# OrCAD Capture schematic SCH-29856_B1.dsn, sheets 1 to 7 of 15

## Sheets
1 01 COVER: title: MIMXRT1020-EVK; rev: B1; company: Freescale Semiconductor; note: SCH-29856, PDF: SPF-29856; note: 6501 William Cannon Drive West; note: Austin, TX 78735-8598
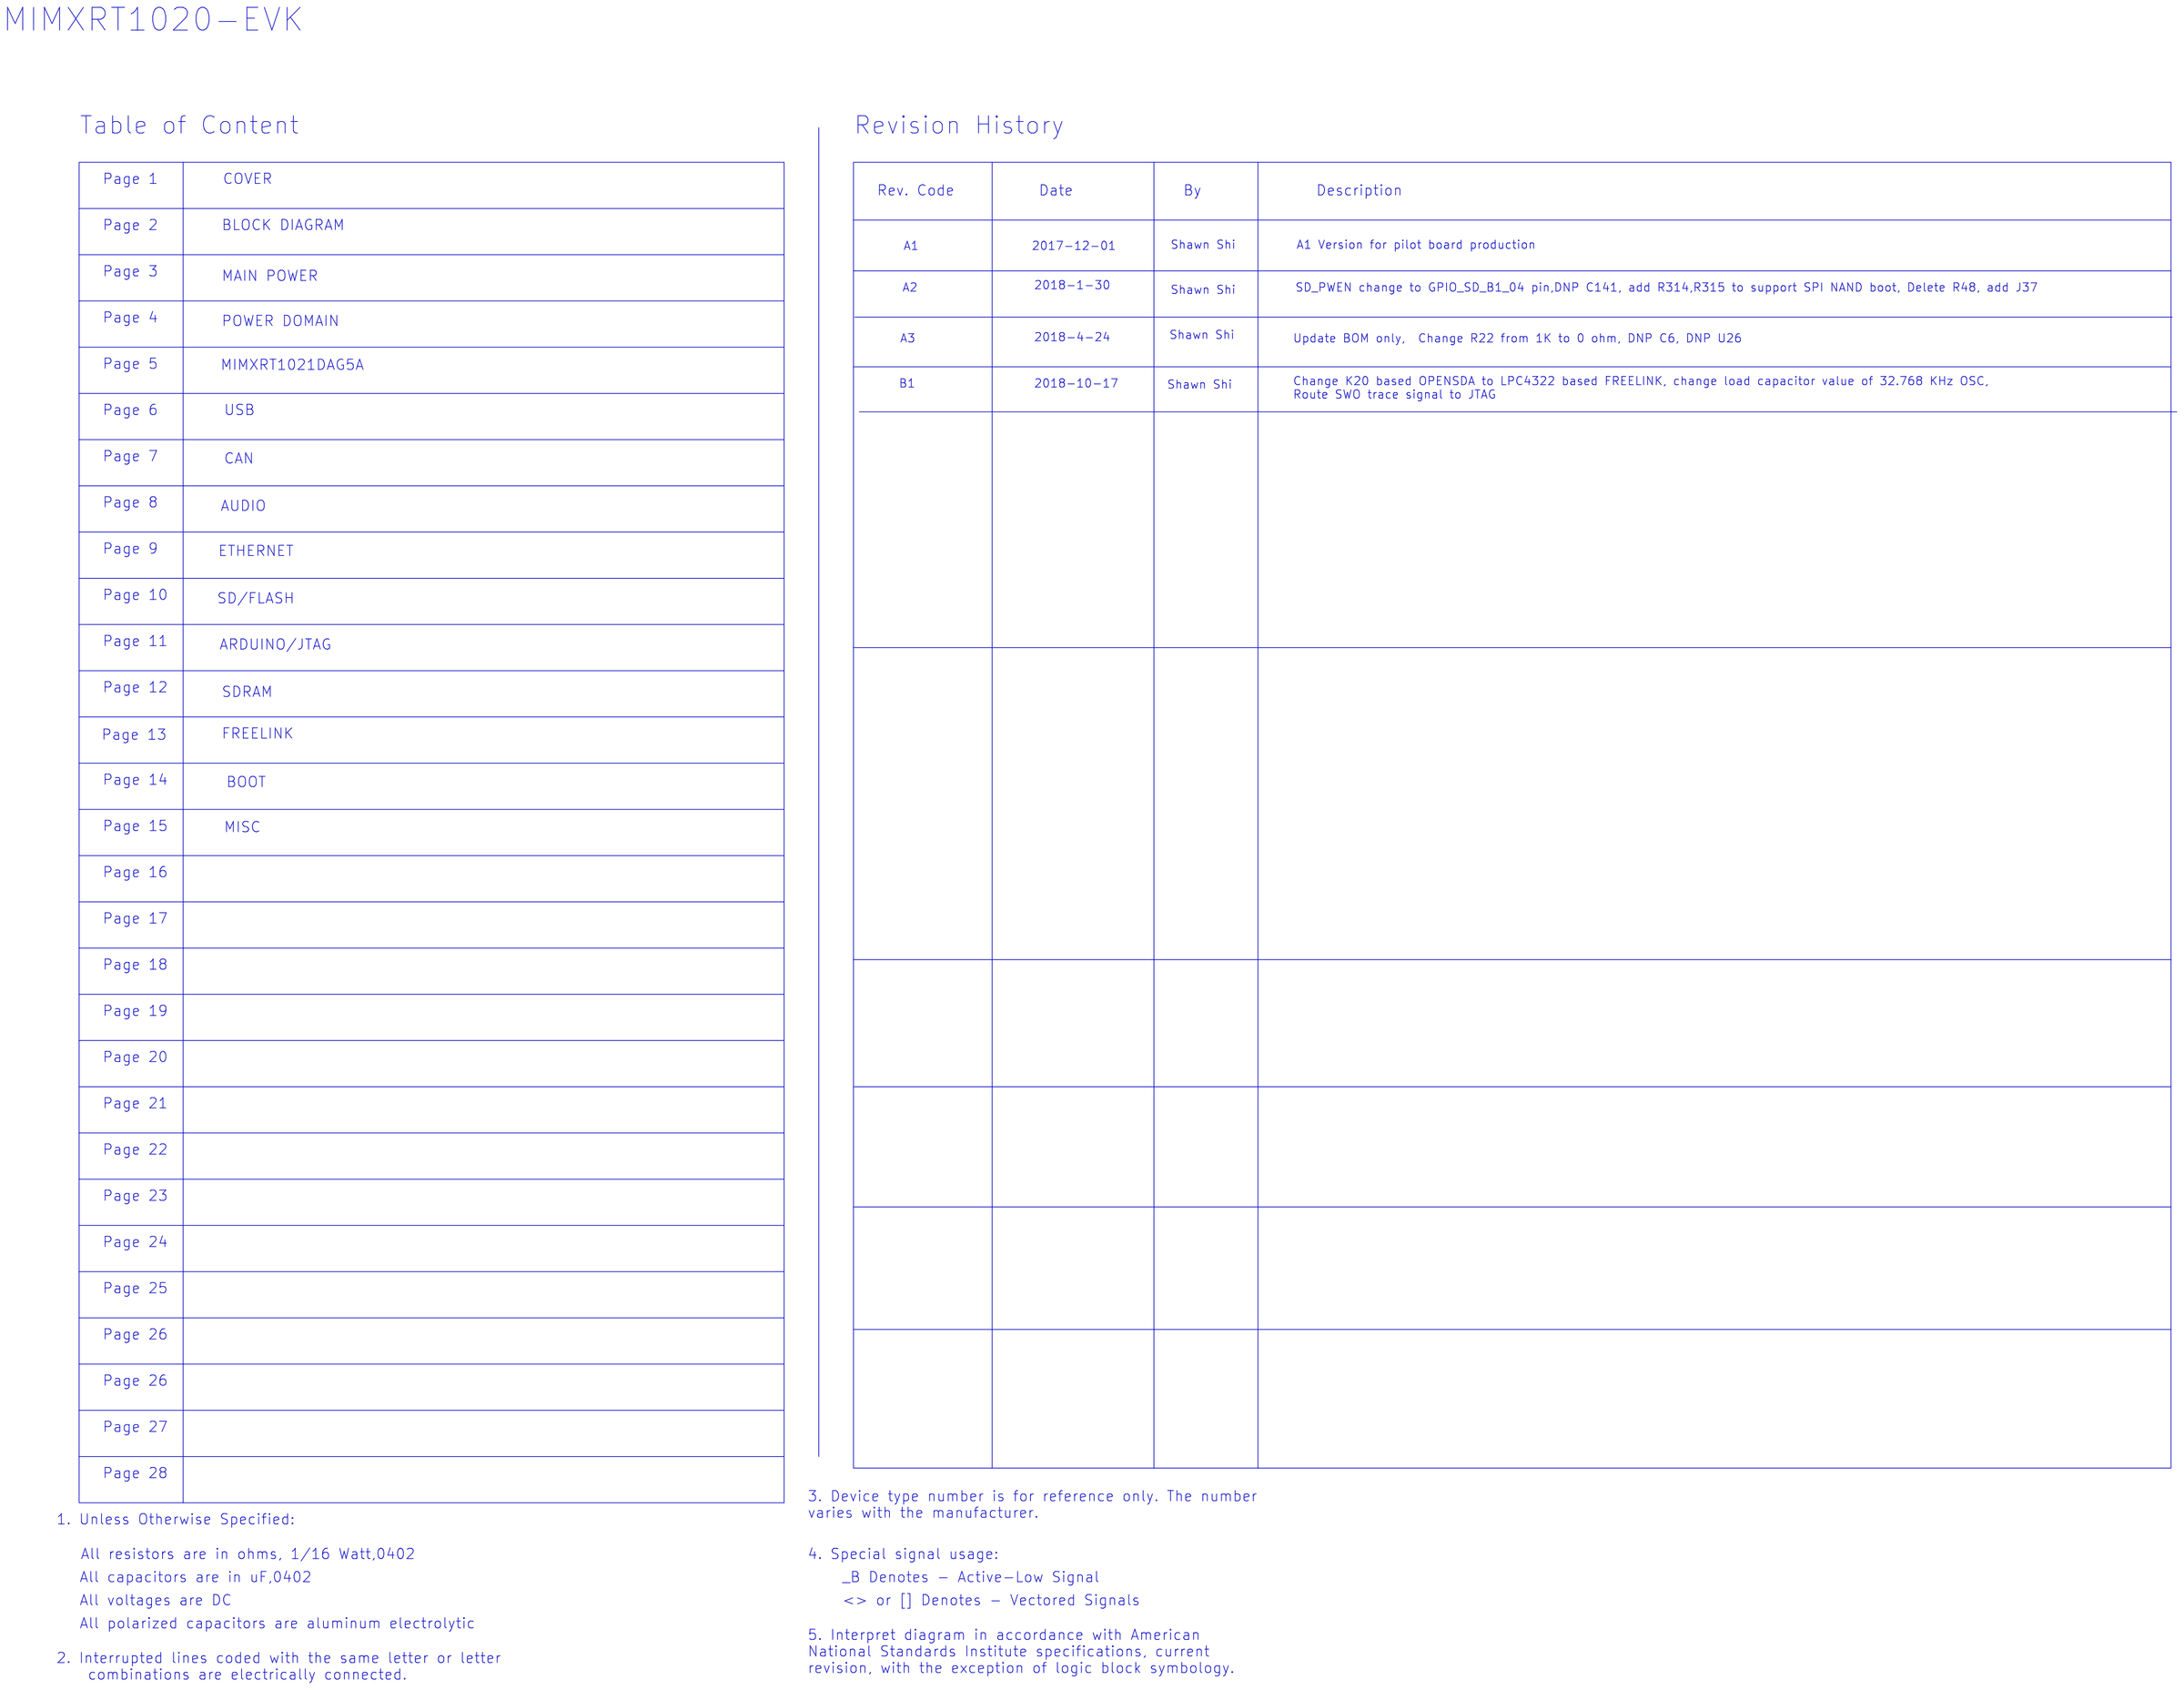
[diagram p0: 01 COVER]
2 02 BLOCK DIAGRAM
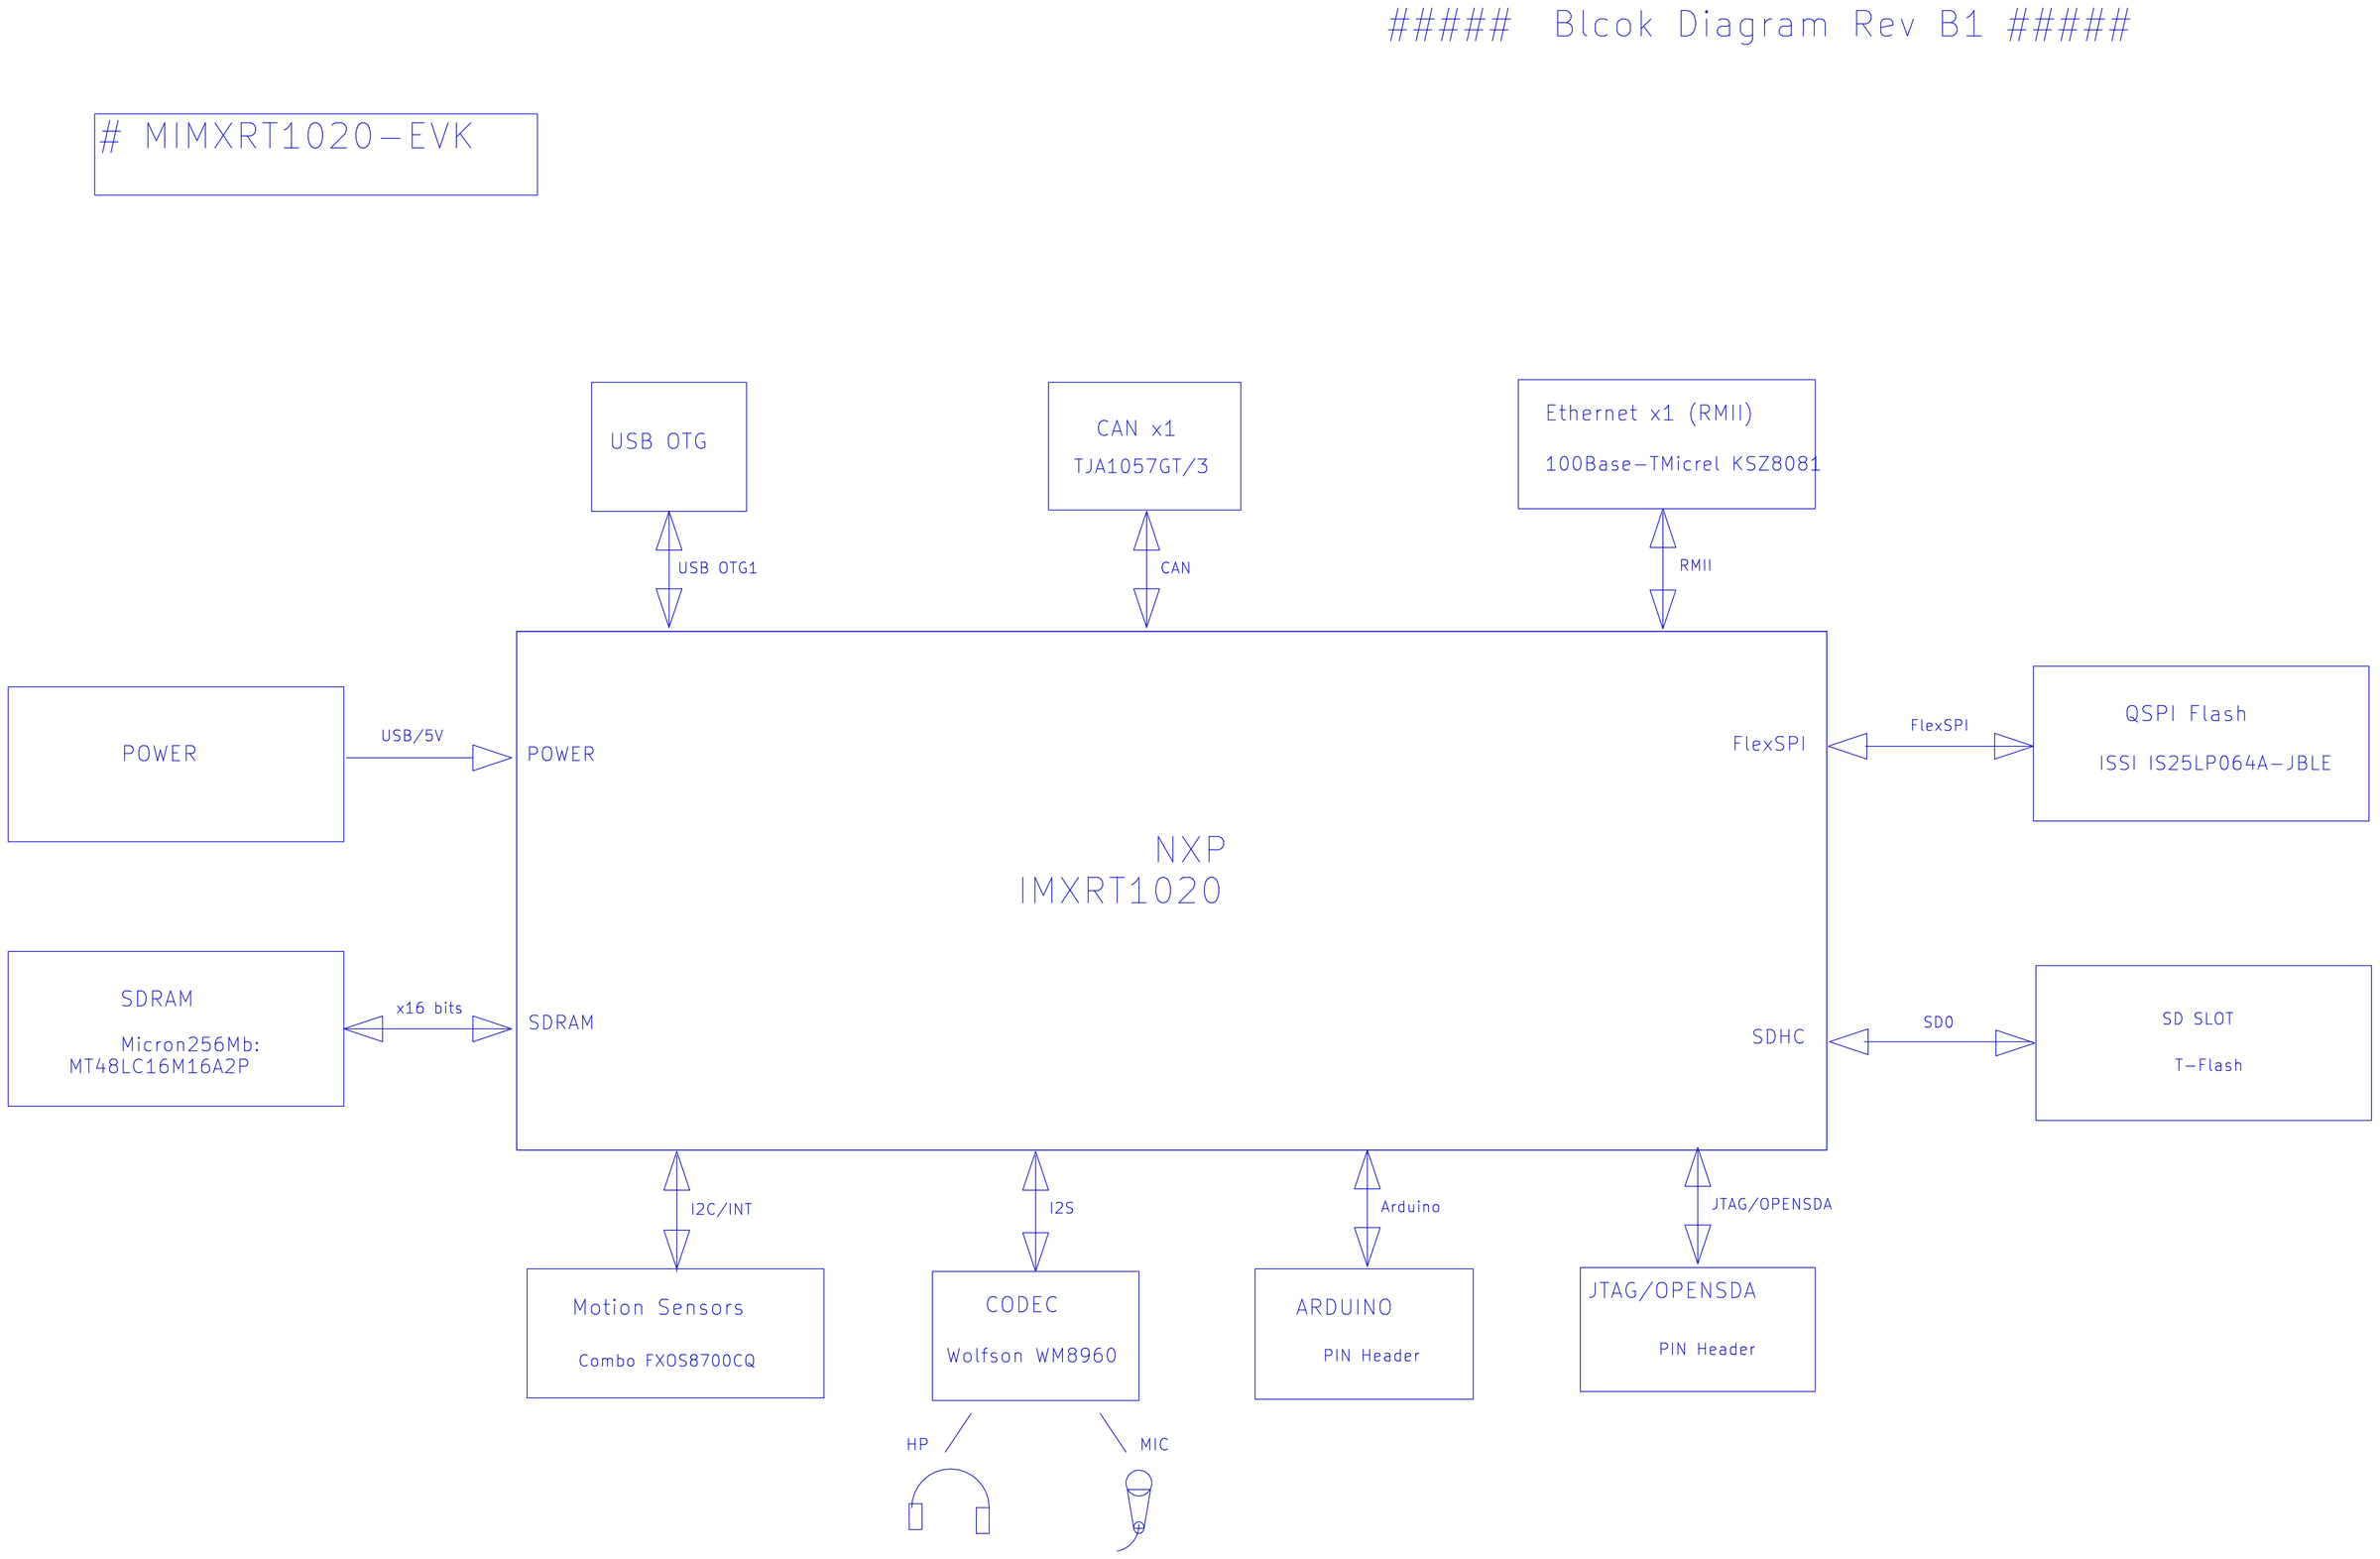
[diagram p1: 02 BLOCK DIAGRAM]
3 03 MAIN POWER: size C
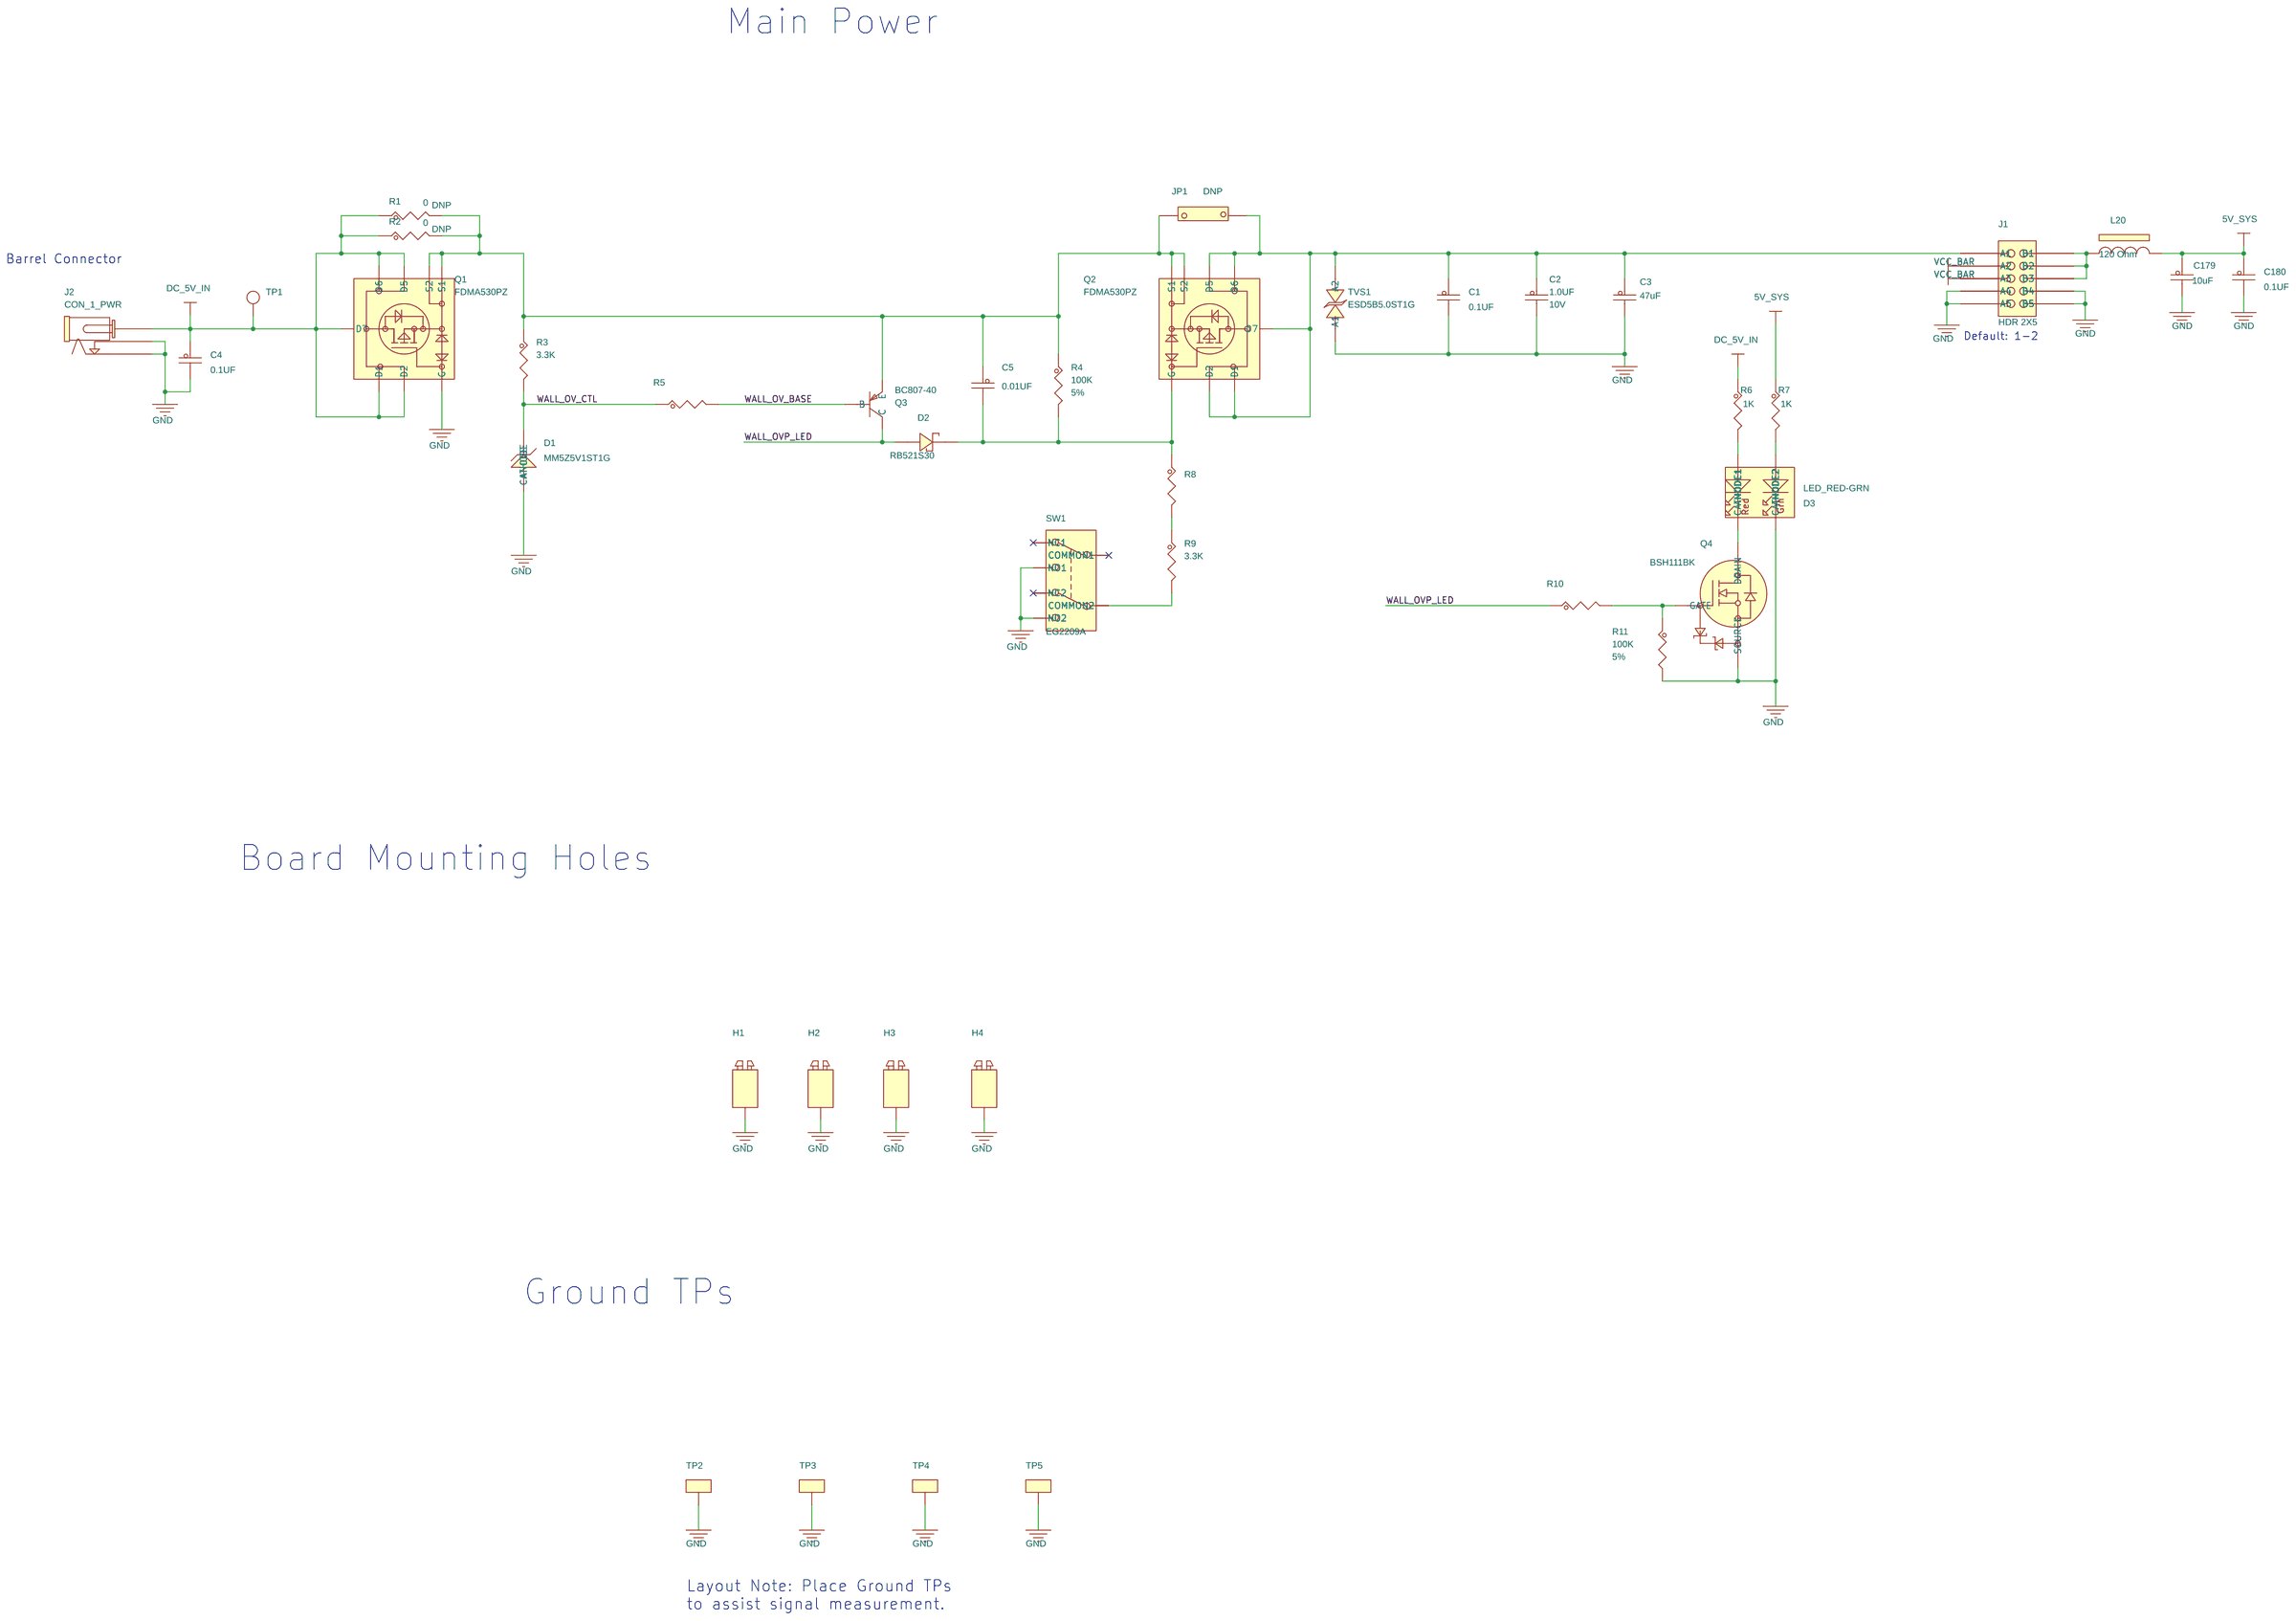
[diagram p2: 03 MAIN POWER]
4 04 POWER DOMAIN: size D
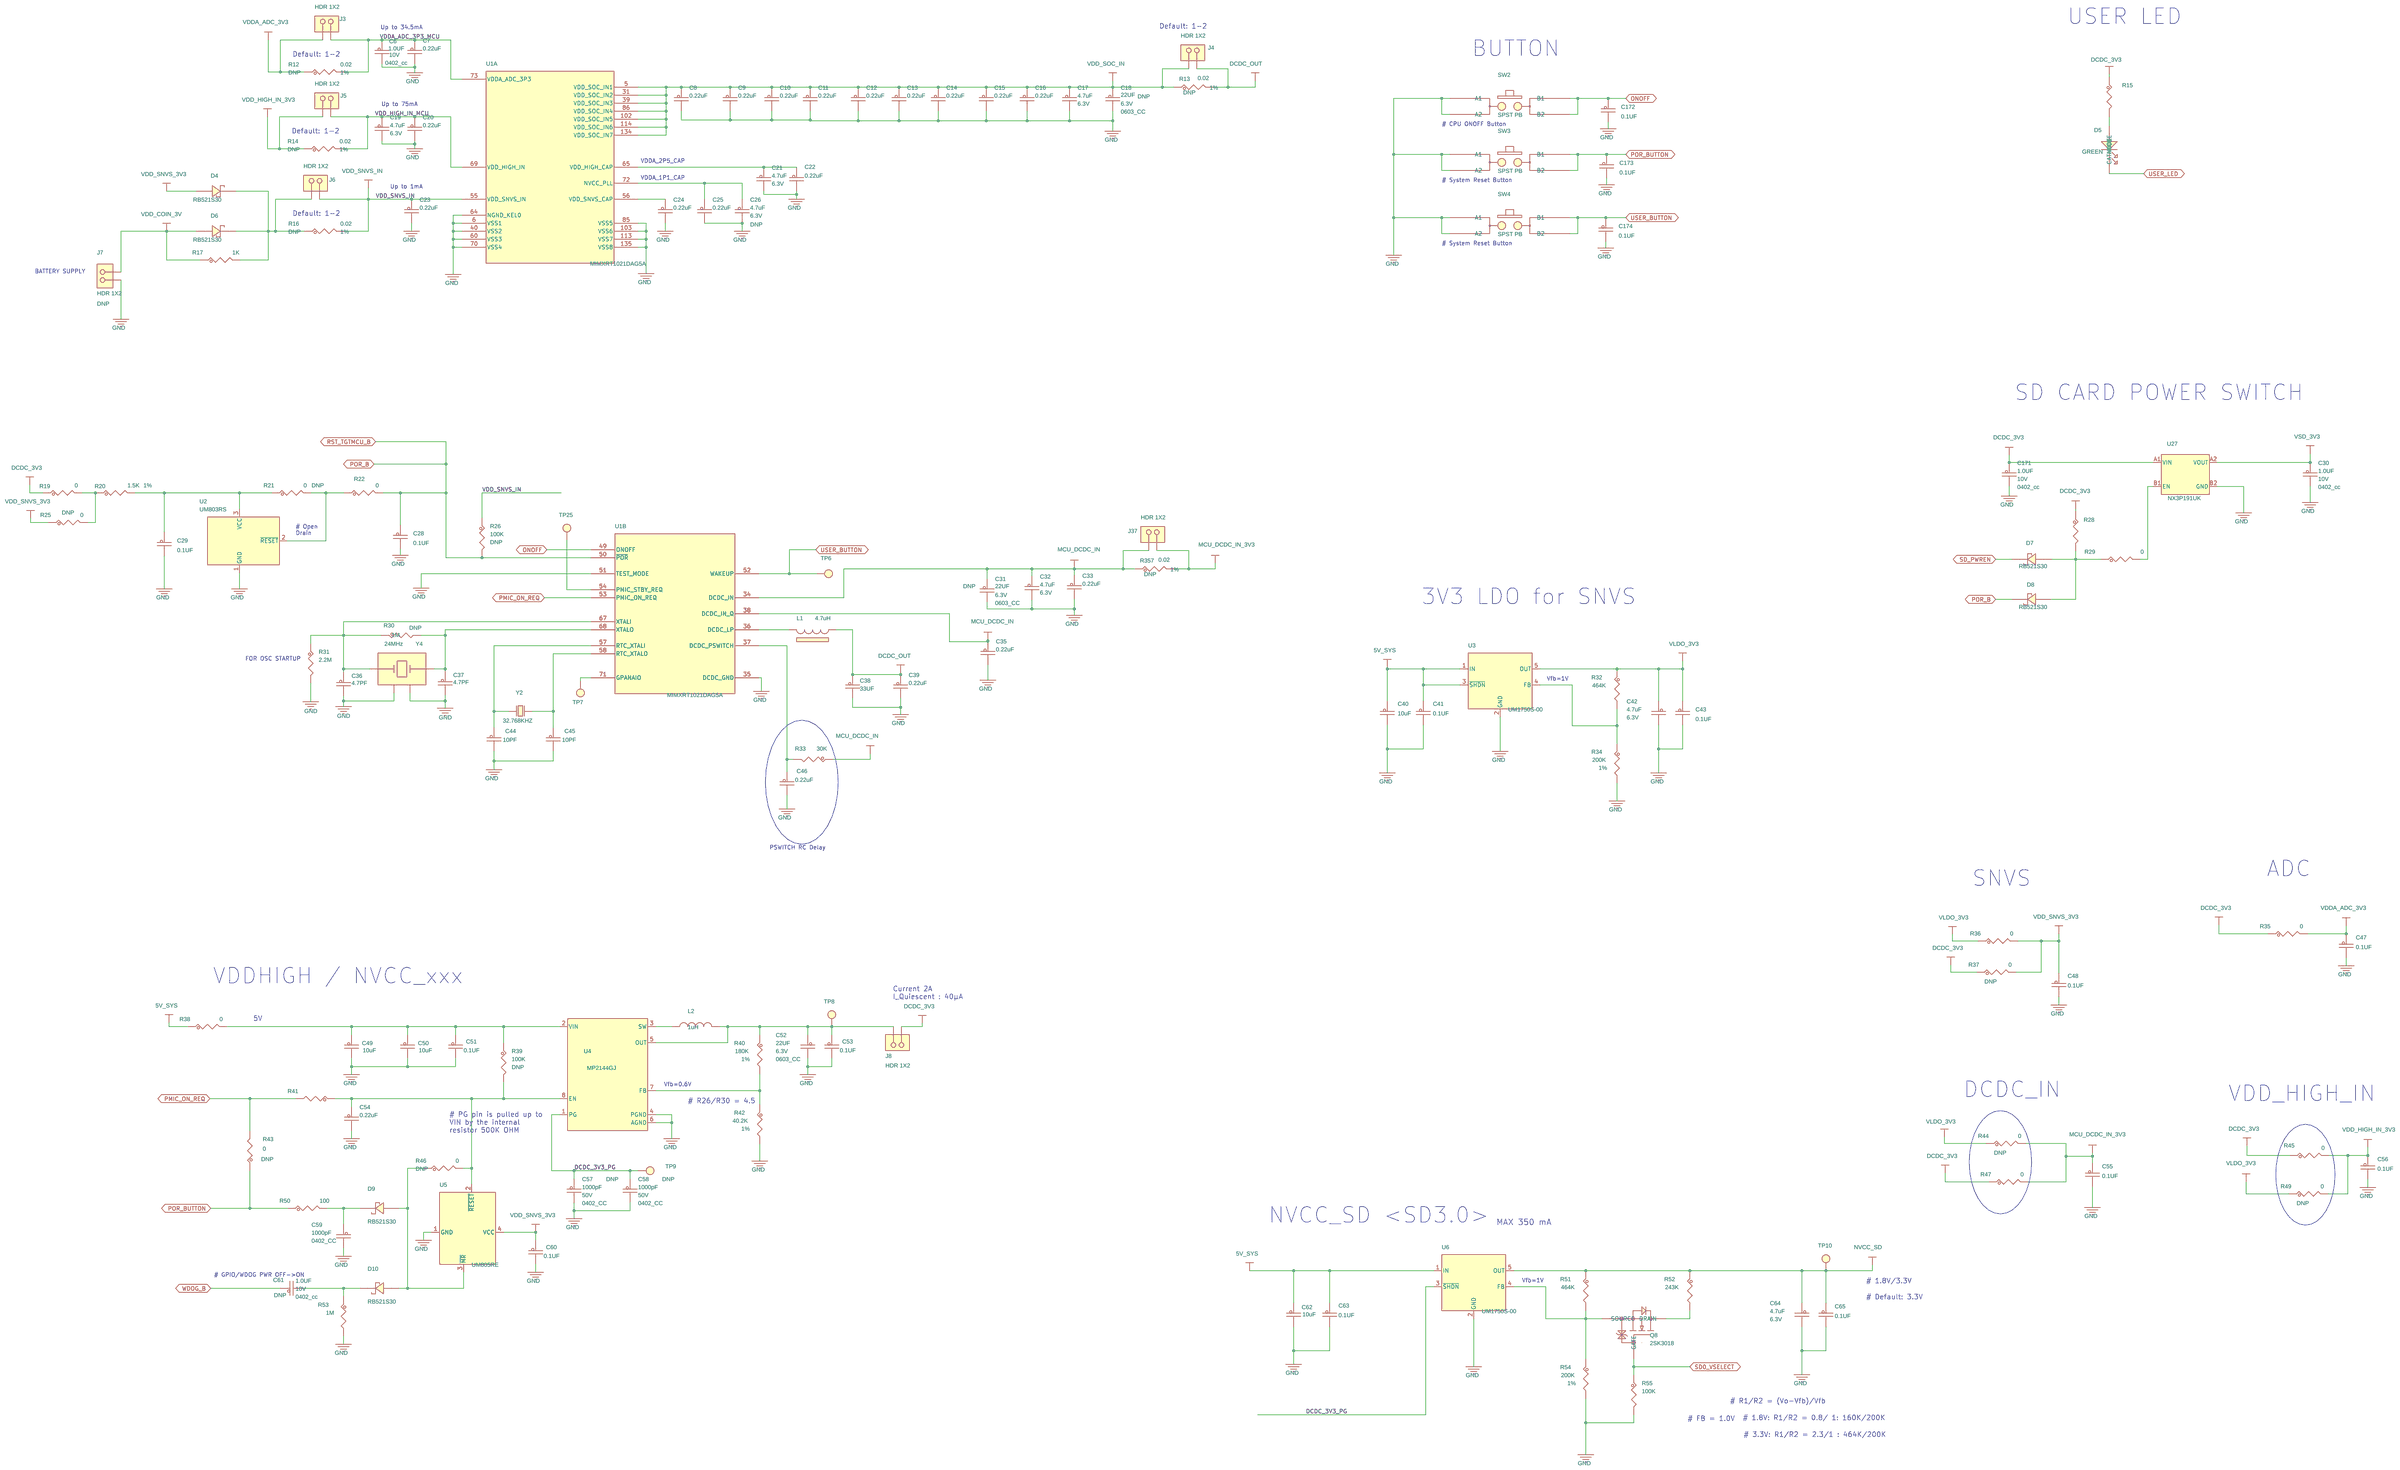
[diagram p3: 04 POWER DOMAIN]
5 05 MIMXRT1021DAG5A: size C
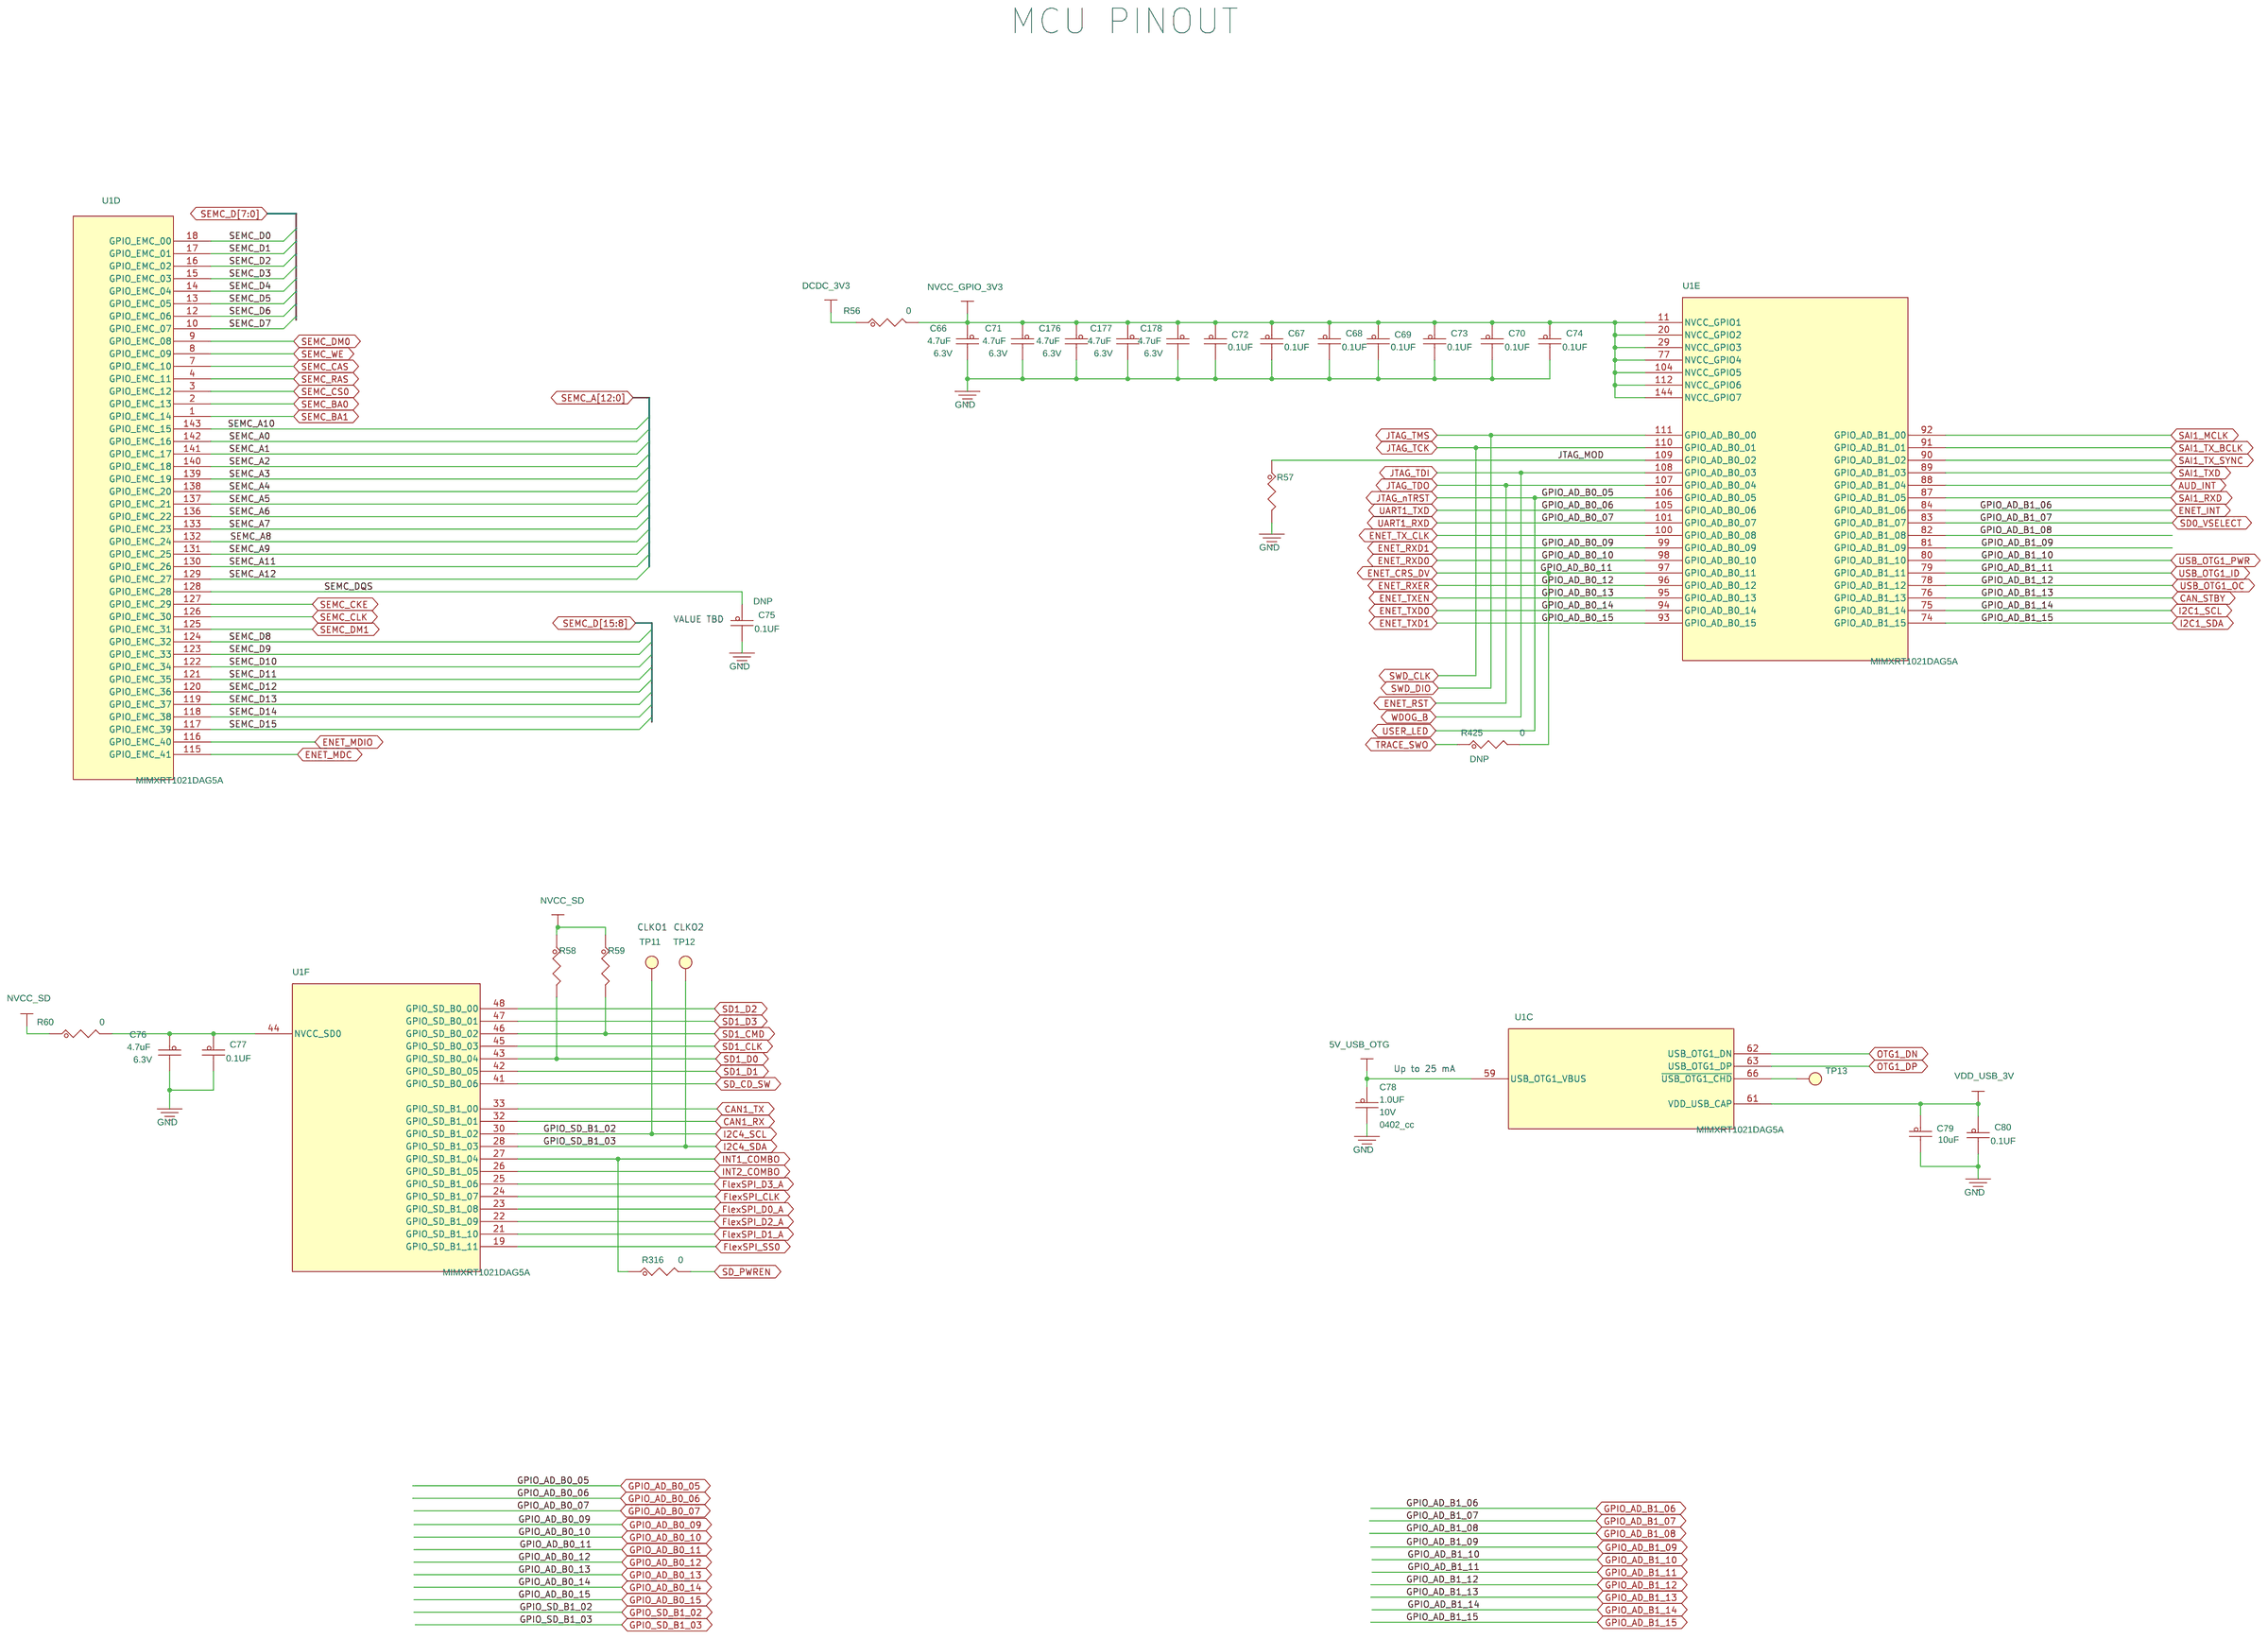
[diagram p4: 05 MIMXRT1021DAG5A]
6 06 USB: size C
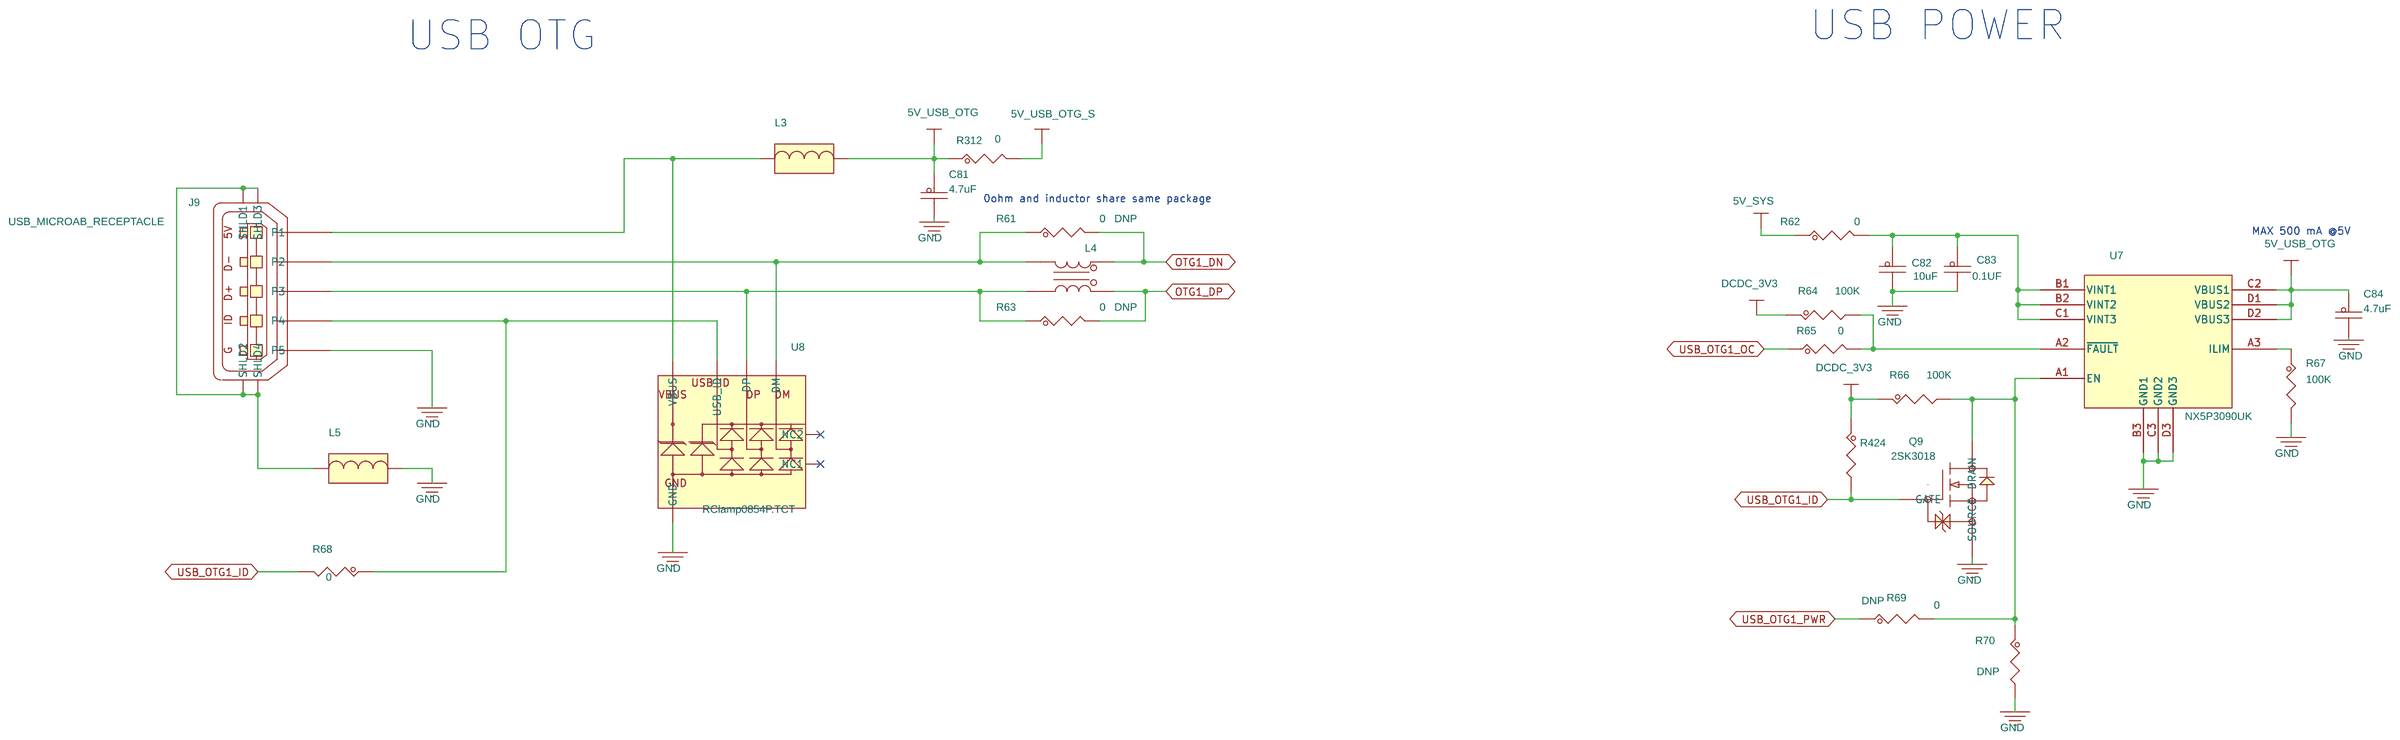
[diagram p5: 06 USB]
7 07 CAN: size C
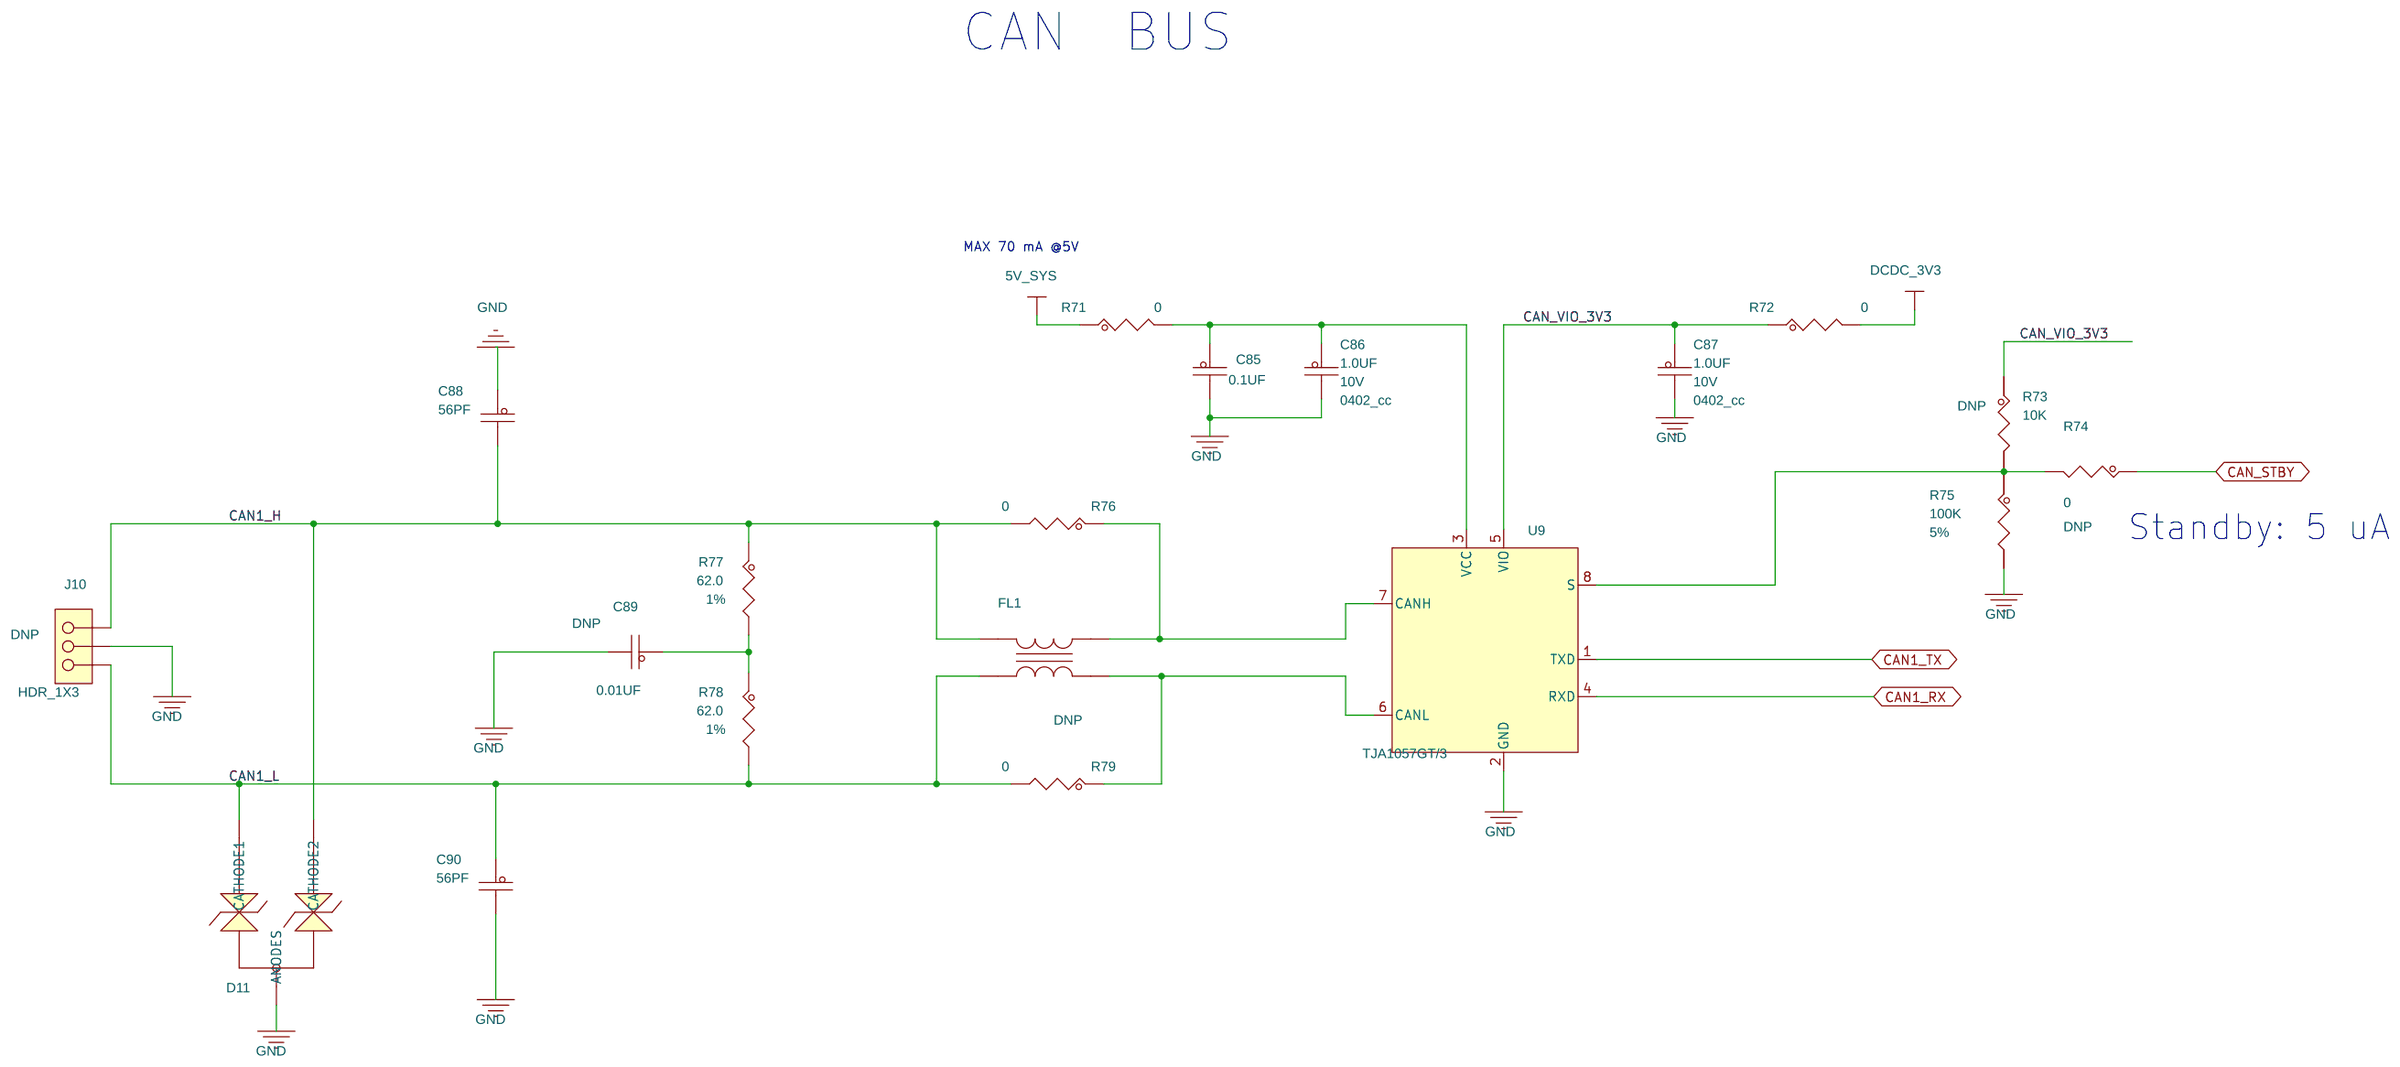
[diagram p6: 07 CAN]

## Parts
sheet 03 MAIN POWER
C1  0.1UF  [CC0402_25]
C2  1.0UF  [0402_CC]
C3  47uF  [CC1206_OV]
C4  0.1UF  [CC0402_25]
C5  0.01UF  [CC0402_25]
C179  10uF  [CC0603_OV]
C180  0.1UF  [CC0402_25]
D1  MM5Z5V1ST1G  [sod_523_1p4]
D2  RB521S30  [SOD523]
D3  LED_RED-GRN  [LED_DUAL_3025MM_SM]
H1  .635" LONG  [spacer_139t]
H2  .635" LONG  [spacer_139t]
H3  .635" LONG  [spacer_139t]
H4  .635" LONG  [spacer_139t]
J1  HDR 2X5  [hdr205]
J2  CON_1_PWR  [con3_pwr_th]
JP1  SHORT_100mil  [100MIL_TH]
L20  120 Ohm  [0402_CC]
Q1  FDMA530PZ  [MLP6_2X2MM_SLUG]
Q2  FDMA530PZ  [MLP6_2X2MM_SLUG]
Q3  BC807-40  [SOT-23]
Q4  BSH111BK  [SOT23_A]
R1  0  [0402_CC]
R2  0  [0402_CC]
R3  3.3K  [RC0402_25]
R4  100K  [0402_CC]
R5  10K  [0402_CC]
R6  1K  [0402_CC]
R7  1K  [0402_CC]
R8  2.2K  [RC0402_25]
R9  3.3K  [RC0402_25]
R10  10K  [0402_CC]
R11  100K  [0402_CC]
SW1  EG2209A  [sw6_dpdt_11x6mm]
TP1  TPAD_030  [TPAD_030]
TP2  5006  [tp_th_063]
TP3  5006  [tp_th_063]
TP4  5006  [tp_th_063]
TP5  5006  [tp_th_063]
TVS1  ESD5B5.0ST1G  [diode2_sod523]
sheet 04 POWER DOMAIN
C6  1.0UF  [0402_cc]
C7  0.22uF  [0402_CC]
C8  0.22uF  [0402_CC]
C9  0.22uF  [0402_CC]
C10  0.22uF  [0402_CC]
C11  0.22uF  [0402_CC]
C12  0.22uF  [0402_CC]
C13  0.22uF  [0402_CC]
C14  0.22uF  [0402_CC]
C15  0.22uF  [0402_CC]
C16  0.22uF  [0402_CC]
C17  4.7uF  [0402_CC]
C18  22UF  [0603_CC]
C19  4.7uF  [0402_CC]
C20  0.22uF  [0402_CC]
C21  4.7uF  [0402_CC]
C22  0.22uF  [0402_CC]
C23  0.22uF  [0402_CC]
C24  0.22uF  [0402_CC]
C25  0.22uF  [0402_CC]
C26  4.7uF  [0402_CC]
C28  0.1UF  [CC0402_25]
C29  0.1UF  [CC0402_25]
C30  1.0UF  [0402_cc]
C31  22UF  [0603_CC]
C32  4.7uF  [0402_CC]
C33  0.22uF  [0402_CC]
C35  0.22uF  [0402_CC]
C36  4.7PF  [0402_CC]
C37  4.7PF  [0402_CC]
C38  33UF  [CC1210]
C39  0.22uF  [0402_CC]
C40  10uF  [CC0603_OV]
C41  0.1UF  [CC0402_25]
C42  4.7uF  [0402_CC]
C43  0.1UF  [CC0402_25]
C44  10PF  [0402_CC]
C45  10PF  [0402_CC]
C46  0.22uF  [0402_CC]
C47  0.1UF  [CC0402_25]
C48  0.1UF  [CC0402_25]
C49  10uF  [CC0603_OV]
C50  10uF  [CC0603_OV]
C51  0.1UF  [CC0402_25]
C52  22UF  [0603_CC]
C53  0.1UF  [CC0402_25]
C54  0.22uF  [0402_CC]
C55  0.1UF  [CC0402_25]
C56  0.1UF  [CC0402_25]
C57  1000pF  [0402_CC]
C58  1000pF  [0402_CC]
C59  1000pF  [0402_CC]
C60  0.1UF  [CC0402_25]
C61  1.0UF  [0402_cc]
C62  10uF  [CC0603_OV]
C63  0.1UF  [CC0402_25]
C64  4.7uF  [0402_CC]
C65  0.1UF  [CC0402_25]
C171  1.0UF  [0402_cc]
C172  0.1UF  [CC0402_25]
C173  0.1UF  [CC0402_25]
C174  0.1UF  [CC0402_25]
D4  RB521S30  [SOD523]
D5  GREEN  [LED_0603]
D6  RB521S30  [SOD523]
D7  RB521S30  [SOD523]
D8  RB521S30  [SOD523]
D9  RB521S30  [SOD523]
D10  RB521S30  [SOD523]
J3  HDR 1X2  [HDR102]
J4  HDR 1X2  [HDR102]
J5  HDR 1X2  [HDR102]
J6  HDR 1X2  [HDR102]
J7  HDR 1X2  [HDR102]
J8  HDR 1X2  [HDR102]
J37  HDR 1X2  [HDR102]
L1  4.7uH  [ind_vls4012e]
L2  1uH  [ind_4020]
Q8  2SK3018  [SOT323_3]
R12  0.02  [RC0603_OV]
R13  0.02  [RC0603_OV]
R14  0.02  [RC0603_OV]
R15  220  [RC0603_OV]
R16  0.02  [RC0603_OV]
R17  1K  [0402_CC]
R19  0  [0402_CC]
R20  1.5K  [0402_CC]
R21  0  [0402_CC]
R22  0  [0402_CC]
R25  0  [0402_CC]
R26  100K  [0402_CC]
R28  10K  [0402_CC]
R29  0  [0402_CC]
R30  1M  [0402_CC]
R31  2.2M  [RC0402_25]
R32  464K  [0402_CC]
R33  30K  [RC0402_25]
R34  200K  [0402_CC]
R35  0  [0402_CC]
R36  0  [0402_CC]
R37  0  [0402_CC]
R38  0  [0402_CC]
R39  100K  [0402_CC]
R40  180K  [0402_CC]
R41  10K  [0402_CC]
R42  40.2K  [0402_CC]
R43  0  [0402_CC]
R44  0  [0402_CC]
R45  0  [0402_CC]
R46  0  [0402_CC]
R47  0  [0402_CC]
R49  0  [0402_CC]
R50  100  [0402_CC]
R51  464K  [0402_CC]
R52  243K  [0402_CC]
R53  1M  [0402_CC]
R54  200K  [0402_CC]
R55  100K  [0402_CC]
R357  0.02  [RC0603_OV]
SW2  SPST PB  [SW4_PB_ESW_SM_P177]
SW3  SPST PB  [SW4_PB_ESW_SM_P177]
SW4  SPST PB  [SW4_PB_ESW_SM_P177]
TP6  TP_35MIL  [testpoint_35mil]
TP7  TP_35MIL  [testpoint_35mil]
TP8  TP_35MIL  [testpoint_35mil]
TP9  TP_35MIL  [testpoint_35mil]
TP10  TP_35MIL  [testpoint_35mil]
TP25  TP_35MIL  [testpoint_35mil]
U1  MIMXRT1021DAG5A  [LQFP144_0P5_20X20MM]  (sections A,B,C,D,E,F)
U2  UM803RS  [sot-23]
U3  UM1750S-00  [sot23-5_a]
U4  MP2144GJ  [tsot23_8_0p65_2x1]
U5  UM805RE  [sot_143]
U6  UM1750S-00  [sot23-5_a]
U27  NX3P191UK  [wlcsp4_0p4_0p8x0p8_smdp]
Y2  32.768KHZ  [XTAL2-3p2x1p5-SM]
Y4  24MHz  [xtl4_2p1x1p7mm_sm]
sheet 05 MIMXRT1021DAG5A
C66  4.7uF  [0402_CC]
C67  0.1UF  [CC0402_25]
C68  0.1UF  [CC0402_25]
C69  0.1UF  [CC0402_25]
C70  0.1UF  [CC0402_25]
C71  4.7uF  [0402_CC]
C72  0.1UF  [CC0402_25]
C73  0.1UF  [CC0402_25]
C74  0.1UF  [CC0402_25]
C75  0.1UF  [CC0402_25]
C76  4.7uF  [0402_CC]
C77  0.1UF  [CC0402_25]
C78  1.0UF  [0402_cc]
C79  10uF  [CC0603_OV]
C80  0.1UF  [CC0402_25]
C176  4.7uF  [0402_CC]
C177  4.7uF  [0402_CC]
C178  4.7uF  [0402_CC]
R56  0  [0402_CC]
R57  10K  [0402_CC]
R58  10K  [0402_CC]
R59  10K  [0402_CC]
R60  0  [0402_CC]
R316  0  [0402_CC]
R425  0  [0402_CC]
TP11  TP_35MIL  [testpoint_35mil]
TP12  TP_35MIL  [testpoint_35mil]
TP13  TP_35MIL  [testpoint_35mil]
sheet 06 USB
C81  4.7uF  [0402_CC]
C82  10uF  [CC0603_OV]
C83  0.1UF  [CC0402_25]
C84  4.7uF  [0402_CC]
J9  USB_MICROAB_RECEPTACLE  [con_usb5_microab_0p65_sm]
L3  330 OHM  [ind_1608]
L4  90OHM  [ind4_choke_0805]
L5  330 OHM  [ind_1608]
Q9  2SK3018  [SOT323_3]
R61  0  [0402_CC]
R62  0  [0402_CC]
R63  0  [0402_CC]
R64  100K  [0402_CC]
R65  0  [0402_CC]
R66  100K  [0402_CC]
R67  100K  [RC0402_25]
R68  0  [0402_CC]
R69  0  [0402_CC]
R70  10K  [0402_CC]
R312  0  [0402_CC]
R424  10K  [0402_CC]
U7  NX5P3090UK  [wlcsp12_0p4_1p38x1p68mm_smdp]
U8  RClamp0854P.TCT  [slp1616p6]
sheet 07 CAN
C85  0.1UF  [CC0402_25]
C86  1.0UF  [0402_cc]
C87  1.0UF  [0402_cc]
C88  56PF  [CC0402_25]
C89  0.01UF  [CC0402_25]
C90  56PF  [CC0402_25]
D11  NUP2105L  [sot-23]
FL1  ACT45B-510-2P  [ind4_4p7x3p4_smt]
J10  HDR_1X3  [HDR103]
R71  0  [0402_CC]
R72  0  [0402_CC]
R73  10K  [0402_CC]
R74  0  [0402_CC]
R75  100K  [0402_CC]
R76  0  [0402_CC]
R77  62.0  [0805_CC]
R78  62.0  [0805_CC]
R79  0  [0402_CC]
U9  TJA1057GT/3  [SO8_1P27_4X5]

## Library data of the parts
C1 C4 C28 C29 C41 C43 C47 C48 C51 C53 C55 C56 C60 C63 C65 C67-C70 C72-C74 C77 C80 C83 C85 C172-C174 C180 = CAP_NP: CAP CER 0.1UF 10V 10% X5R 0402; AGILE_PN: 150-75634; CAD_APPROVED: Yes; FPLIST: CC0402_25,CC0402_HD,0402_CC; HEIGHT: 0.64MM; MFG_NAME01: KEMET; MFG_PN01: C0402C104K8PAC; ROHS: Yes; Tolerance: 10%; VOLTAGE: 10V
C2 = CAP_NP: CAP CER 1.0UF 10V 10% X5R 0402; AGILE_PN: 150-75772; CAD_APPROVED: Yes; FPLIST: CC0402_25,CC0402_HD,0402_CC; HEIGHT: 0.6MM; MFG_NAME01: YAGEO AMERICA; MFG_PN01: CC0402KRX5R6BB105; ROHS: Yes; VOLTAGE: 10V; voltage rating: 10V
C3 = CAP_NP: CAP CER 47UF 6.3V 10% X5R 1206; AGILE_PN: 150-78503; CAD_APPROVED: Yes; FPLIST: CC1206_OV,CC1206,1206_CC; HEIGHT: 1.8MM; MFG_NAME01: MURATA; MFG_PN01: GRM31CR60J476KE19L; ROHS: Yes; Temp_Range: -55°C to +85°C; Tolerance: 10%; VOLTAGE: 6.3V
C5 = CAP_NP: CAP CER 0.01UF 16V 20% X7R 0402; AGILE_PN: 150-30082; CAD_APPROVED: Yes; FPLIST: CC0402_25,CC0402_HD,0402_CC; HEIGHT: 0.56MM; MFG_NAME01: AVX; MFG_PN01: 0402YC103MAT2A; ROHS: Yes; TOL: 20%; Tolerance: 20%; VOLTAGE: 16V
C40 C49 C50 C62 C79 C82 C179 = CAP_NP: CAP CER 10UF 10V 10% X5R 0603; AGILE_PN: 150-78675; CAD_APPROVED: Yes; FPLIST: CC0603_OV,CC0603,0603_CC; HEIGHT: 1.016MM; MFG_NAME01: MURATA; MFG_PN01: GRM188R61A106KE69D; ROHS: Yes; Temp_Range: -55°C ~ 85°C; Tolerance: 10%; VOLTAGE: 10v
D1 = ZDIODE: DIODE ZNR -- 0.2W 5.1V AEC-Q101 SOD523; AGILE_PN: 480-77217; CAD_APPROVED: Yes; HEIGHT: 0.7MM; MFG_NAME01: ON SEMICONDUCTOR; ROHS: Yes
D2 D4 D6-D10 = DIODE_SCHTKY: DIODE SCH RECT 200MA 30V AEC-Q101 SOD-523; AGILE_PN: 480-79672; CAD_APPROVED: Yes; HEIGHT: 0.65MM; MFG_NAME01: NEXPERIA; MFG_PN01: RB521S30,115; ROHS: Yes
D3 = LED_DUAL_SEP_RG: LED RED GRN DUAL 30/25MA SMT; AGILE_PN: 370-75097; CAD_APPROVED: Yes; HEIGHT: 1.1MM; MFG_NAME01: KINGBRIGHT; MFG_PN01: APB3025ESGC-F01; ROHS: Yes
H1-H4 = SPACER: FASTENER, STANDOFF 4.5MMX3.53XM3.0X0.5 ROUND THR .635"L BRASS; AGILE_PN: 280-76498; ASSY_OPT: DNP; CAD_APPROVED: Yes; HEIGHT: 16.13MM; MFG_NAME01: UNICORP; MFG_PN01: MSS251-R-1-A-16; ROHS: Yes
J1 = CONN_HDR_5X2: HDR 2X5 TH 100MIL CTR 338H AU 98L; AGILE_PN: 210-81467; CAD_APPROVED: Yes; HEIGHT: 8.59MM; MFG_NAME01: ANYTRONIC CORPORATION LIMITED; MFG_PN01: 0902S1005011N9T-31RF; ROHS: Yes; Temp_Range: -55DegC to +105DegC
J2 = PHONEJACK-3: CON 1 PWR PLUG RA TH 2.5A 20V -- 441H SN/NI; AGILE_PN: 210-80780; CAD_APPROVED: Yes; HEIGHT: 11.2MM; MFG_NAME01: SHENZHEN ATOM TECHNOLOGY CO.,LTD; MFG_PN01: DC060024202; ROHS: Yes
JP1 = JUMPER1x2: CON 2 JUMPER MALE 2.54MM SP 157H AU; AGILE_PN: 210-30004; ASSY_OPT: DNP; CAD_APPROVED: Yes; HEIGHT: 4MM; MFG_NAME01: PRECI-DIP CONNECTION TECHNOLOGY; MFG_PN01: 999-11-110-10; ROHS: Yes
L20 = INDUCTOR_FERRITE: IND FER BEAD 120 OHM@100MHZ 0.5A 25% 0402; AGILE_PN: 180-77771; CAD_APPROVED: Yes; FPLIST: IND_0402,0402_CC; HEIGHT: 0.55MM; MFG_NAME01: Murata; MFG_PN01: BLM15AG121SN1D; PART_TYPE: FERRITE\BEAD; ROHS: Yes; Tolerance: 25%
Q1 Q2 = FDMA530PZ: TRAN PMOS PWR 30V 6.8A; AGILE_PN: 480-77039; CAD_APPROVED: Yes; HEIGHT: 0.8MM; MFG_NAME01: FAIRCHILD; ROHS: Yes
Q3 = PNP: TRAN PNP GEN -45VCE 500MA; AGILE_PN: 480-75918; CAD_APPROVED: Yes; HEIGHT: 1.1MM; MFG_NAME01: PHILIPS SEMICONDUCTOR; ROHS: Yes
Q4 = NMOS_2N7002BKW_3P: TRAN NMOS SW FET 55V 210mA SOT23; AGILE_PN: 480-79704; CAD_APPROVED: Yes; HEIGHT: 1.1MM; MFG_NAME01: NEXPERIA; MFG_PN01: BSH111BKR; ROHS: Yes
R1 R2 R21 R25 R37 R43 R44 R46 R49 R61 R63 R69 R74 R425 = RES: RES MF ZERO OHM 1/16W 5% 0402; AGILE_PN: 470-75394; ASSY_OPT: DNP; CAD_APPROVED: Yes; FPLIST: RC0402_25,RC0402_HD,RC0402_X2,0402_CC; HEIGHT: 0.45 MM; MFG_NAME01: ROHM; MFG_PN01: MCR01MZPJ000; ROHS: Yes; Tolerance: 5%
R3 R9 = RES: RES MF 3.3K 1/16W 5% 0402; AGILE_PN: 470-76064; CAD_APPROVED: Yes; FPLIST: RC0402_25,RC0402_HD,0402_CC; HEIGHT: 0.40 MM; MFG_NAME01: YAGEO AMERICA; MFG_PN01: RC0402JR-073K3L; ROHS: Yes; TOL: 5%; Tolerance: 5%
R4 R11 R64 R66 R75 = RES: RES MF 100K 1/16W 5% 0402; AGILE_PN: 470-75597; CAD_APPROVED: Yes; FPLIST: RC0402_25,RC0402_HD,0402_CC; HEIGHT: 0.40 MM; MFG_NAME01: VENKEL COMPANY; MFG_PN01: CR0402-16W-104JT; ROHS: Yes; TOL: 5%; Temp_Range: -55C to +155C; Tolerance: 5%
R5 R10 R28 R57-R59 = RES: RES MF 10K 1/16W 5% 0402; AGILE_PN: 470-75557; CAD_APPROVED: Yes; FPLIST: RC0402_25,RC0402_HD,0402_CC; HEIGHT: 0.4 MM; MFG_NAME01: VISHAY INTERTECHNOLOGY; MFG_PN01: CRCW040210K0JNED; ROHS: Yes; TOL: 5%; Tolerance: 5%
R6 R7 R17 = RES: RES MF 1.0K 1/16W 5% 0402; AGILE_PN: 470-75555; CAD_APPROVED: Yes; FPLIST: RC0402_25,RC0402_HD,RC0402_X2,0402_CC; HEIGHT: 0.41mm; MFG_NAME01: VISHAY INTERTECHNOLOGY; MFG_PN01: CRCW04021K00JNED; ROHS: Yes; Tolerance: 5%
R8 = RES: RES MF 2.2K 1/16W 5% 0402; AGILE_PN: 470-76602; CAD_APPROVED: Yes; FPLIST: RC0402_25,RC0402_HD,0402_CC; HEIGHT: 0.4 MM; MFG_NAME01: YAGEO AMERICA; MFG_PN01: RC0402JR-072K2L; ROHS: Yes; TOL: 5%; Tolerance: 5%
SW1 = SW_DPDT_3: SW DPDT SLD 0.1A 12V L=4 TH; AGILE_PN: 510-77598; CAD_APPROVED: Yes; HEIGHT: 9.5MM; MFG_NAME01: E SWITCH; ROHS: Yes
TP1 = TestLoop: TEST POINT PAD 30MIL DIA SMT, NO PART TO ORDER; AGILE_PN: 211-76642; CAD_APPROVED: Yes; HEIGHT: 0.1MM; MFG_NAME01: NOTACOMPONENT; MFG_PN01: NOTACOMPONENT; ROHS: Yes
TP2-TP5 = TEST_POINT: TEST POINT BLK 70X220 MIL TH; AGILE_PN: 210-30155; CAD_APPROVED: Yes; HEIGHT: 5.6MM; MFG_NAME01: Keystone Electronics; ROHS: Yes
TVS1 = DIODE_TVS_BIDIR: DIODE SUPPRESSOR 16A@30NS 5V@1UA SOD-523; AGILE_PN: 480-76937; CAD_APPROVED: Yes; HEIGHT: 0.7MM; MFG_NAME01: on semiconductor; ROHS: Yes
C6 C30 C78 C86 C87 C171 = CAP_NP: CAP CER 1.0UF 10V 10% X5R 0402; AGILE_PN: 150-75772; CAD_APPROVED: Yes; FPLIST: CC0402_25,CC0402_HD,0402_CC; HEIGHT: 0.6MM; MFG_NAME01: YAGEO AMERICA; MFG_PN01: CC0402KRX5R6BB105; ROHS: Yes; VOLTAGE: 10V
C7-C16 C20 C22-C25 C33 C35 C39 C46 C54 = CAP_NP: CAP CER 0.22UF 6.3V 20% X5R 0402; AGILE_PN: 150-76271; CAD_APPROVED: Yes; FPLIST: CC0402_25,CC0402_HD,0402_CC; HEIGHT: 0.55MM; MFG_NAME01: MURATA; MFG_PN01: GRM155R60J224ME01; ROHS: Yes; Tolerance: 20%; VOLTAGE: 6.3V
C17 C19 C21 C32 C42 C64 C66 C71 C76 C176-C178 = CAP_NP: CAP CER 4.7UF 6.3V 20% X5R 0402; AGILE_PN: 150-78463; CAD_APPROVED: Yes; FPLIST: CC0402_25,CC0402_HD,0402_CC; HEIGHT: 0.65MM; MFG_NAME01: TDK; MFG_PN01: C1005X5R0J475M050BC; ROHS: Yes; Tolerance: 20%; VOLTAGE: 6.3V; voltage rating: 6.3V
C18 C31 = CAP_NP: CAP CER 22UF 6.3V 20% X5R 0603; AGILE_PN: 150-78467; ASSY_OPT: DNP; CAD_APPROVED: Yes; FPLIST: CC0603_OV,CC0603,0603_CC; HEIGHT: 1MM; MFG_NAME01: Samsung; MFG_PN01: CL10A226MQ8NRNE; ROHS: Yes; Tolerance: 20%; VOLTAGE: 6.3V; voltage rating: 6.3V
C26 = CAP_NP: CAP CER 4.7UF 6.3V 20% X5R 0402; AGILE_PN: 150-78463; ASSY_OPT: DNP; CAD_APPROVED: Yes; FPLIST: CC0402_25,CC0402_HD,0402_CC; HEIGHT: 0.65MM; MFG_NAME01: TDK; MFG_PN01: C1005X5R0J475M050BC; ROHS: Yes; Tolerance: 20%; VOLTAGE: 6.3V; voltage rating: 6.3V
C36 C37 = CAP_NP: CAP CER 4.7PF 50V 0.25PF C0G 0402; AGILE_PN: 150-76335; CAD_APPROVED: Yes; FPLIST: CC0402_25,CC0402_HD,0402_CC; HEIGHT: 0.55MM; MFG_NAME01: MURATA; MFG_PN01: GRM1555C1H4R7CA01D; ROHS: Yes; Tolerance: 0.25pF; VOLTAGE: 50V
C38 = CAP_NP: CAP CER 33UF 6.3V 20% X5R 1210; AGILE_PN: 150-76796; CAD_APPROVED: Yes; FPLIST: CC1210,1210_CC; HEIGHT: 2.2MM; MFG_NAME01: MURATA; MFG_PN01: GRM32DR60J336ME19L; ROHS: Yes; Tolerance: 20%; VOLTAGE: 6.3V
C44 C45 = CAP_NP: CAP CER 10PF 50V 5% C0G 0402; AGILE_PN: 150-75265; CAD_APPROVED: YES; FPLIST: CC0402_25,CC0402_HD,0402_CC; HEIGHT: 0.635MM; MFG_NAME01: AVX; MFG_PN01: 04025A100JAT2A; ROHS: Yes; Tolerance: 5%; VOLTAGE: 50V
C52 = CAP_NP: CAP CER 22UF 6.3V 20% X5R 0603; AGILE_PN: 150-78467; CAD_APPROVED: Yes; FPLIST: CC0603_OV,CC0603,0603_CC; HEIGHT: 1MM; MFG_NAME01: Samsung; MFG_PN01: CL10A226MQ8NRNE; ROHS: Yes; Tolerance: 20%; VOLTAGE: 6.3V; voltage rating: 6.3V
C57 C58 = CAP_NP: CAP CER 1000PF 50V 5% C0G 0402; AGILE_PN: 150-76334; ASSY_OPT: DNP; CAD_APPROVED: Yes; FPLIST: CC0402_25,CC0402_HD,0402_CC; HEIGHT: 0.55MM; MFG_NAME01: MURATA; MFG_PN01: GRM1555C1H102JA01D; ROHS: Yes; Tolerance: 5%; VOLTAGE: 50V
C59 = CAP_NP: CAP CER 1000PF 50V 5% C0G 0402; AGILE_PN: 150-76334; CAD_APPROVED: Yes; FPLIST: CC0402_25,CC0402_HD,0402_CC; HEIGHT: 0.55MM; MFG_NAME01: MURATA; MFG_PN01: GRM1555C1H102JA01D; ROHS: Yes; Tolerance: 5%; VOLTAGE: 50V
C61 = CAP_NP: CAP CER 1.0UF 10V 10% X5R 0402; AGILE_PN: 150-75772; ASSY_OPT: DNP; CAD_APPROVED: Yes; FPLIST: CC0402_25,CC0402_HD,0402_CC; HEIGHT: 0.6MM; MFG_NAME01: YAGEO AMERICA; MFG_PN01: CC0402KRX5R6BB105; ROHS: Yes; VOLTAGE: 10V
D5 = LED: LED GRN SGL 25MA 0603; AGILE_PN: 370-76549; CAD_APPROVED: Yes; HEIGHT: 0.85MM; MFG_NAME01: KINGBRIGHT; MFG_PN01: KPT-1608SGC; ROHS: Yes
J3-J6 J8 J37 = CONN_HDR_2X1: HDR 1X2 TH 100MIL SP 339H AU 98L; AGILE_PN: 210-81490; CAD_APPROVED: Yes; HEIGHT: 8.59MM; MFG_NAME01: ANYTRONIC CORPORATION LIMITED; MFG_PN01: 0901S0202011N9T-31RF; ROHS: Yes; Temp_Range: -55°C to +105°C
J7 = CONN_HDR_2X1: HDR 1X2 TH 100MIL SP 339H AU 98L; AGILE_PN: 210-81490; ASSY_OPT: DNP; CAD_APPROVED: Yes; HEIGHT: 8.59MM; MFG_NAME01: ANYTRONIC CORPORATION LIMITED; MFG_PN01: 0901S0202011N9T-31RF; ROHS: Yes; Temp_Range: -55°C to +105°C
L1 = IND_FERRITE: IND WW FER 4.7uH@1MHz 1.4A 20% 4012; AGILE_PN: 180-78674; CAD_APPROVED: Yes; HEIGHT: 1.2MM; MFG_NAME01: TDK; MFG_PN01: VLS4012ET-4R7M; PART_TYPE: FERRITE; ROHS: Yes; Temp_Range: -40C to +105C; Tolerance: 20%
L2 = IND: IND PWR 1UH@100KHZ 2.6A 30% SMT; AGILE_PN: 180-77797; CAD_APPROVED: Yes; HEIGHT: 2.2MM; MFG_NAME01: Shenzhen Sunlord Electronics Co., Ltd; MFG_PN01: SWPA4020S1R0NT; PART_TYPE: INDUCTOR\POWER; ROHS: Yes; TOL: 30%; Tolerance: 30%
Q8 Q9 = 2SK3018: TRANS MOSFET N-CH 30V .1A SOT-323; AGILE_PN: 480-75317; CAD_APPROVED: Yes; HEIGHT: 0.9MM; MFG_NAME01: ROHM; MFG_PN01: 2SK3018T106; ROHS: Yes
R12-R14 R16 R357 = RES: RES MF 0.02 OHM 1/10W 1% 0603; AGILE_PN: 470-80199; ASSY_OPT: DNP; CAD_APPROVED: Yes; FPLIST: RC0603_OV,RC0603,0603_CC; HEIGHT: 0.457MM; MFG_NAME01: VISHAY INTERTECHNOLOGY; MFG_PN01: WSL0603R0200FEA; ROHS: Yes; TOL: 1%; Tolerance: 1%
R15 = RES: RES MF 220 OHM 1/10W 5% 0603; AGILE_PN: 470-30297; CAD_APPROVED: Yes; FPLIST: RC0603_OV,RC0603,0603_CC; HEIGHT: 0.6MM; MFG_NAME01: YAGEO AMERICA; MFG_PN01: RC0603JR-07220RL; ROHS: Yes; Tolerance: 5%
R19 R22 R29 R35 R36 R38 R45 R47 R56 R60 R62 R65 R68 R71 R72 R76 R79 R312 R316 = RES: RES MF ZERO OHM 1/16W 5% 0402; AGILE_PN: 470-75394; CAD_APPROVED: Yes; FPLIST: RC0402_25,RC0402_HD,RC0402_X2,0402_CC; HEIGHT: 0.45 MM; MFG_NAME01: ROHM; MFG_PN01: MCR01MZPJ000; ROHS: Yes; Tolerance: 5%
R20 = RES: RES MF 1.5K 1/16W 1% 0402; AGILE_PN: 470-80487; CAD_APPROVED: Yes; FPLIST: RC0402_25,RC0402_HD,0402_CC; HEIGHT: 0.4MM; MFG_NAME01: BOURNS; MFG_PN01: CR0402-FX-1501GLF; ROHS: Yes; Tolerance: 1%
R26 R39 = RES: RES MF 100K 1/16W 5% 0402; AGILE_PN: 470-75597; ASSY_OPT: DNP; CAD_APPROVED: Yes; FPLIST: RC0402_25,RC0402_HD,0402_CC; HEIGHT: 0.40 MM; MFG_NAME01: VENKEL COMPANY; MFG_PN01: CR0402-16W-104JT; ROHS: Yes; Temp_Range: -55C to +155C; Tolerance: 5%
R30 = RES: RES MF 1M 1/10W 5% AEC-Q200 0402; AGILE_PN: 470-79978; ASSY_OPT: DNP; CAD_APPROVED: Yes; FPLIST: RC0402_25,RC0402_HD,0402_CC; HEIGHT: 0.4MM; MFG_NAME01: KOA SPEER; MFG_PN01: RK73B1ETTP105J; ROHS: Yes; Temp_Range: -55&#8451; to 155&#8451;; Tolerance: 5%
R31 = RES: RES MF 2.2M 1/10W 1% AEC-Q200 0402; AGILE_PN: 470-31210; CAD_APPROVED: Yes; FPLIST: RC0402_25,RC0402_HD,0402_CC; HEIGHT: 0.40 MM; MFG_NAME01: KOA SPEER; MFG_PN01: RK73H1ETTP2204F; ROHS: Yes; Temp_Range: -55C to +155C; Tolerance: 1%
R32 R51 = RES: RES MF 464K 1/10W 1% AEC-Q200 0402; AGILE_PN: 470-31135; CAD_APPROVED: Yes; FPLIST: RC0402_25,RC0402_HD,0402_CC; HEIGHT: 0.40 MM; MFG_NAME01: KOA SPEER; MFG_PN01: RK73H1ETTP4643F; ROHS: Yes; Temp_Range: -55C to +155C; Tolerance: 1%
R33 = RES: RES MF 30K 1/16W 1% 0402; AGILE_PN: 470-76590; CAD_APPROVED: Yes; FPLIST: RC0402_25,RC0402_HD,0402_CC; HEIGHT: 0.4MM; MFG_NAME01: THYE MING TECH CO LTD; MFG_PN01: CR02FL6-30K; ROHS: Yes; Tolerance: 1%
R34 R54 = RES: RES MF 200K 1/10W 1% AEC-Q200 0402; AGILE_PN: 470-31093; CAD_APPROVED: Yes; FPLIST: RC0402_25,RC0402_HD,0402_CC; HEIGHT: 0.40 MM; MFG_NAME01: KOA SPEER; MFG_PN01: RK73H1ETTP2003F; ROHS: Yes; Temp_Range: -55C to +155C; Tolerance: 1%
R40 = RES: RES MF 180K 1/10W 1% AEC-Q200 0402; AGILE_PN: 470-31088; CAD_APPROVED: Yes; FPLIST: RC0402_25,RC0402_HD,0402_CC; HEIGHT: 0.40 MM; MFG_NAME01: KOA SPEER; MFG_PN01: RK73H1ETTP1803F; ROHS: Yes; Temp_Range: -55C to +155C; Tolerance: 1%
R41 R424 = RES: RES MF 10K 1/16W 5% 0402; AGILE_PN: 470-75557; CAD_APPROVED: Yes; FPLIST: RC0402_25,RC0402_HD,0402_CC; HEIGHT: 0.4 MM; MFG_NAME01: VISHAY INTERTECHNOLOGY; MFG_PN01: CRCW040210K0JNED; ROHS: Yes; Tolerance: 5%
R42 = RES: RES MF 40.2K  1/16W 1% 0402; AGILE_PN: 470-31015; CAD_APPROVED: Yes; FPLIST: RC0402_25,RC0402_HD,0402_CC; HEIGHT: 0.40 MM; MFG_NAME01: YAGEO AMERICA; MFG_PN01: RC0402FR-0740K2L; ROHS: Yes; Temp_Range: -55C to +155C; Tolerance: 1%
R50 = RES: RES MF 100 OHM 1/16W 1% 0402; AGILE_PN: 470-30454; CAD_APPROVED: Yes; FPLIST: RC0402_25,RC0402_HD,0402_CC; HEIGHT: 0.4 MM; MFG_NAME01: THYE MING TECH CO LTD; MFG_PN01: CR-02FL6--100R; ROHS: Yes; Tolerance: 1%
R52 = RES: RES MF 243K 1/10W 1% AEC-Q200 0402; AGILE_PN: 470-31102; CAD_APPROVED: Yes; FPLIST: RC0402_25,RC0402_HD,0402_CC; HEIGHT: 0.40 MM; MFG_NAME01: KOA SPEER; MFG_PN01: RK73H1ETTP2433F; ROHS: Yes; Temp_Range: -55C to +155C; Tolerance: 1%
R53 = RES: RES MF 1M 1/10W 5% AEC-Q200 0402; AGILE_PN: 470-79978; CAD_APPROVED: Yes; FPLIST: RC0402_25,RC0402_HD,0402_CC; HEIGHT: 0.4MM; MFG_NAME01: KOA SPEER; MFG_PN01: RK73B1ETTP105J; ROHS: Yes; Temp_Range: -55&#8451; to 155&#8451;; Tolerance: 5%
R55 = RES: RES MF 100K 1/16W 5% 0402; AGILE_PN: 470-75597; CAD_APPROVED: Yes; FPLIST: RC0402_25,RC0402_HD,0402_CC; HEIGHT: 0.40 MM; MFG_NAME01: VENKEL COMPANY; MFG_PN01: CR0402-16W-104JT; ROHS: Yes; Temp_Range: -55C to +155C; Tolerance: 5%
SW2-SW4 = SW_PB_ESW: SW SPST MOM NO PB TACT 50mA 50V SMT; AGILE_PN: 510-77562; CAD_APPROVED: Yes; HEIGHT: 5MM; MFG_NAME01: E SWITCH; MFG_PN01: TL3301AF260QG/TR; ROHS: Yes
TP6-TP13 TP25 = T_POINT_R: TEST POINT PAD .035 SMT, no part to order; AGILE_PN: 510-75618; CAD_APPROVED: Yes; HEIGHT: 0.1MM; ROHS: Yes
U1 = IMXRT1020_LQFP144P: IC CPU ARM Cortex-M7 500MHZ 1.3V LQFP144; AGILE_PN: 330-77054; CAD_APPROVED: Yes; HEIGHT: 1.6 MM; MFG_NAME01: NXP SEMICONDUCTORS; ROHS: Yes
U2 = SGM803_SOT23-3P: IC VOLT MONITOR 2.63V RST VTH 1-5.5V AUTO SOT-23; AGILE_PN: 315-80553; CAD_APPROVED: Yes; HEIGHT: 1.25MM; MFG_NAME01: Union Semiconductor, Inc; ROHS: Yes
U3 U6 = UM1750S-00_5P: IC VREG LDO ADJ 1-5V 350mA 2.5-6V SOT23-5; AGILE_PN: 315-80554; CAD_APPROVED: Yes; HEIGHT: 1.25MM; MFG_NAME01: Union Semiconductor, Inc; ROHS: Yes
U4 = MP2144GJ_TSOT23_8P: IC SYNC STEP-DOWN SW 1.2MHZ 0.6V 2A 2.5-5.5V TSOT23-8; AGILE_PN: 315-80508; CAD_APPROVED: Yes; HEIGHT: 1MM; MFG_NAME01: MONOLITHIC POWER SYSTEMS; ROHS: Yes
U5 = UM805_4P: IC VOLT MONITOR 2.63V VTH RST 1-5.5V SOT143; AGILE_PN: 315-80564; CAD_APPROVED: Yes; HEIGHT: 1.22MM; MFG_NAME01: Union Semiconductor, Inc; ROHS: Yes
U27 = ADP172_CSP_4P: IC LOAD SW 1A 1.1-3.6V WLCSP4; AGILE_PN: 315-81585; CAD_APPROVED: Yes; HEIGHT: 0.54MM; MFG_NAME01: NXP SEMICONDUCTORS; MFG_PN01: NX3P191UK,012; ROHS: Yes; Temp_Range: -40C to +85C
Y2 = CRYSTAL: XTAL 32.768KHZ 7PF 20PPM -- SMT; AGILE_PN: 230-78102; CAD_APPROVED: Yes; HEIGHT: 0.9MM; MFG_NAME01: EPSON ELECTRONICS; MFG_PN01: FC-135 32.7680KA-AG3; ROHS: Yes
Y4 = XTAL_13: XTAL 24MHZ -- 20PPM 2.0X1.6MM SMD; AGILE_PN: 230-78216; CAD_APPROVED: Yes; HEIGHT: 0.7MM; MFG_NAME01: MURATA; MFG_PN01: XRCGB24M000F2P29R0; ROHS: Yes; Temp_Range: -30C to 85C
C75 = CAP_NP: CAP CER 0.1UF 10V 10% X5R 0402; AGILE_PN: 150-75634; ASSY_OPT: DNP; CAD_APPROVED: Yes; FPLIST: CC0402_25,CC0402_HD,0402_CC; HEIGHT: 0.64MM; MFG_NAME01: KEMET; MFG_PN01: C0402C104K8PAC; ROHS: Yes; Tolerance: 10%; VOLTAGE: 10V
C81 C84 = CAP_NP: CAP CER 4.7UF 6.3V 20% X5R 0402; AGILE_PN: 150-78463; CAD_APPROVED: Yes; FPLIST: CC0402_25,CC0402_HD,0402_CC; HEIGHT: 0.65MM; MFG_NAME01: TDK; MFG_PN01: C1005X5R0J475M050BC; ROHS: Yes; TOL: 20%; Tolerance: 20%; VOLTAGE: 6.3V
J9 = USB_MINI_AB_RECEPTACLE: CON 5 USB MICRO_AB RA SKT SMT 0.65MM SP 110H AU; AGILE_PN: 211-80104; CAD_APPROVED: Yes; HEIGHT: 2.8MM; MFG_NAME01: ANYTRONIC CORPORATION LIMITED; MFG_PN01: 23971101#LCP-58RF; ROHS: Yes; Temp_Range: -55&#8451; to 105&#8451;
L3 L5 = BEAD: IND FER BEAD 330OHM@100MHZ 1.7A 0603; AGILE_PN: 180-78156; CAD_APPROVED: Yes; HEIGHT: 0.95MM; MFG_NAME01: TDK; MFG_PN01: MPZ1608S331A; PART_TYPE: FERRITE\BEAD; ROHS: Yes; TOL: 25%; Tolerance: 25%
L4 = DLW43: IND CHK 90 OHM@100MHZ 330MA 25% 0805; AGILE_PN: 180-76336; CAD_APPROVED: Yes; HEIGHT: 1MM; MFG_NAME01: MURATA; MFG_PN01: DLW21HN900SQ2L; PART_TYPE: CHOKE; ROHS: Yes; Tolerance: 25%
R67 = RES: RES MF 100K 1/16W 1% 0402; AGILE_PN: 470-76240; CAD_APPROVED: Yes; FPLIST: RC0402_25,RC0402_HD,0402_CC; HEIGHT: 0.4MM; MFG_NAME01: YAGEO AMERICA; MFG_PN01: RC0402FR-07100KL; ROHS: Yes; Tolerance: 1%
R70 R73 = RES: RES MF 10K 1/16W 5% 0402; AGILE_PN: 470-75557; ASSY_OPT: DNP; CAD_APPROVED: Yes; FPLIST: RC0402_25,RC0402_HD,0402_CC; HEIGHT: 0.4 MM; MFG_NAME01: VISHAY INTERTECHNOLOGY; MFG_PN01: CRCW040210K0JNED; ROHS: Yes; Tolerance: 5%
U7 = NX5P3090UK_WLCSP12: IC USB PD TYPE C CURRENT LIMITED PWR SW 2.5-5.5V WLCSP12; AGILE_PN: 312-81574; CAD_APPROVED: Yes; HEIGHT: 0.565 MM; MFG_NAME01: NXP SEMICONDUCTORS; MFG_PN01: NX5P3090UK,012; ROHS: Yes
U8 = RCLAMP1654P_NEW: DIODE TVS ARRAY 3 5.5V SLP1616P6; AGILE_PN: 480-78843; CAD_APPROVED: Yes; HEIGHT: 0.65MM; MFG_NAME01: SEMTECH CORP; ROHS: Yes
C88 C90 = CAP_NP: CAP CER 56PF 50V 5% C0G 0402; AGILE_PN: 150-30269; CAD_APPROVED: Yes; FPLIST: CC0402_25,CC0402_HD,0402_CC; HEIGHT: 0.55 MM; MFG_NAME01: MURATA; MFG_PN01: GRM1555C1H560JA01D; ROHS: Yes; Tolerance: 5%; VOLTAGE: 50V
C89 = CAP_NP: CAP CER 0.01UF 16V 20% X7R 0402; AGILE_PN: 150-30082; ASSY_OPT: DNP; CAD_APPROVED: Yes; FPLIST: CC0402_25,CC0402_HD,0402_CC; HEIGHT: 0.56MM; MFG_NAME01: AVX; MFG_PN01: 0402YC103MAT2A; ROHS: Yes; TOL: 20%; Tolerance: 20%; VOLTAGE: 16V
D11 = DIODE_NUP2105L: DIODE DUAL LINE CAN BUS PROTECTOR 27V 350W SOT-23; AGILE_PN: 480-77157; CAD_APPROVED: Yes; HEIGHT: 1.11MM; MFG_NAME01: On semiconductor; MFG_PN01: NUP2105LT1G; ROHS: Yes
FL1 = FILTER_4P: FILTER COMMON MODE 51uH@100kHZ 200mA 50V AEC-Q200 SMT; AGILE_PN: 180-77935; ASSY_OPT: DNP; CAD_APPROVED: Yes; HEIGHT: 3MM; MFG_NAME01: TDK; MFG_PN01: B82787C513H2; PART_TYPE: FILTER; ROHS: Yes
J10 = CONN_HDR_3X1: HDR 1X3 TH 100MIL SP 338H AU 98L; AGILE_PN: 210-81491; ASSY_OPT: DNP; CAD_APPROVED: Yes; HEIGHT: 8.59MM; MFG_NAME01: ANYTRONIC CORPORATION LIMITED; MFG_PN01: 0901S0203011N9T-31RF; ROHS: Yes; Temp_Range: -55°C to +105°C
R77 R78 = RES: RES MF 62.0 OHM 1/4W 1% AEC-Q200 0805; AGILE_PN: 470-78674; CAD_APPROVED: Yes; FPLIST: RC0805_OV,RC0805,0805_CC; HEIGHT: 0.6 MM; MFG_NAME01: KOA SPEER; MFG_PN01: RK73H2ATTD62R0F; ROHS: Yes; Tolerance: 1%
U9 = TJA1057GT3_8P: IC XCVR CAN 4.75-5.25V/2.95-5.25V AEC-Q100 SO8; AGILE_PN: 312-81479; CAD_APPROVED: Yes; HEIGHT: 1.75MM; MFG_NAME01: NXP SEMICONDUCTORS; ROHS: Yes

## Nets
5V_SYS: C40.1 C41.1 C62.1 C63.1 C179.1 C180.1 L20.2 R7.1 R38.1 R62.1 R71.1 U3.1(IN) U3.3(~{SHDN}) U6.1(IN) ; also on sheet 8 15
5V_USB_OTG: C78.1 C81.1 C84.1 L3.2 R312.1 U1.59(USB_OTG1_VBUS) U7.C2(VBUS1) U7.D1(VBUS2) U7.D2(VBUS3)
5V_USB_OTG_S: J1.3(A2) R312.2
GND: C1.2 C2.2 C3.2 C4.2 C6.2 C7.2 C8.2 C9.2 C10.2 C11.2 C12.2 C13.2 C14.2 C15.2 C16.2 C17.2 C18.2 C19.2 C20.2 C21.2 C22.2 C23.2 C24.2 C25.2 C26.2 C28.2 C29.2 C30.2 C31.2 C32.2 C33.2 C35.2 C36.2 C37.2 C38.2 C39.2 C40.2 C41.2 C42.2 C43.2 C44.2 C45.2 C46.2 C47.2 C48.2 C49.2 C50.2 C51.2 C52.2 C53.2 C54.2 C55.2 C56.2 C57.2 C58.2 C59.2 C60.2 C62.2 C63.2 C64.2 C65.2 C66.2 C67.2 C68.2 C69.2 C70.2 C71.2 C72.2 C73.2 C74.2 C75.2 C76.2 C77.2 C78.2 C79.2 C80.2 C81.2 C82.2 C83.2 C84.2 C85.2 C86.2 C87.2 C88.1 C89.2 C90.2 C171.2 C172.2 C173.2 C174.2 C176.2 C177.2 C178.2 C179.2 C180.2 D1.A(ANODE) D3.4(CATHODE2) D11.3(ANODES) H1.1(NC) H2.1(NC) H3.1(NC) H4.1(NC) J1.7(A4) J1.8(B4) J1.9(A5) J1.10(B5) J2.2 J2.3 J7.1 J9.5(P5) J10.2 L5.2 Q1.3(G) Q4.2(SOURCE) Q9.1(SOURCE) R11.2 R31.2 R34.2 R42.2 R53.2 R54.2 R55.2 R57.2 R67.2 R70.2 R75.2 SW1.3(NO1) SW1.6(NO2) SW2.1(A1) SW2.2(A2) SW3.1(A1) SW3.2(A2) SW4.1(A1) SW4.2(A2) TP2.1 TP3.1 TP4.1 TP5.1 TVS1.1(A1) U1.6(VSS1) U1.35(DCDC_GND) U1.40(VSS2) U1.51(TEST_MODE) U1.60(VSS3) U1.64(NGND_KEL0) U1.70(VSS4) U1.85(VSS5) U1.103(VSS6) U1.113(VSS7) U1.135(VSS8) U2.1(GND) U3.2(GND) U4.4(PGND) U4.6(AGND) U5.1(GND) U6.2(GND) U7.B3(GND1) U7.C3(GND2) U7.D3(GND3) U8.7(GND) U9.2(GND) U27.B2(GND) Y4.2 Y4.4 ; also on sheet 8 9 10 11 12 13 14 15
P5V_SDA_S: J1.5(A3) ; also on sheet 11
VDD_COIN_3V: D6.A J7.2 R17.1
VDD_HIGH_IN_3V3: C56.1 J5.1 R14.1 R45.2 R49.2
VDD_HIGH_IN_MCU: C19.1 C20.1 J5.2 R14.2 U1.69(VDD_HIGH_IN)
VDD_SNVS_3V3: C48.1 C60.1 D4.A R25.1 R36.2 R37.2 U5.4(VCC)
VDD_SNVS_IN: C23.1 J6.2 R16.2 R26.1 U1.55(VDD_SNVS_IN)
VDD_SOC_IN: C8.1 C9.1 C10.1 C11.1 C12.1 C13.1 C14.1 C15.1 C16.1 C17.1 C18.1 J4.1 R13.1 U1.5(VDD_SOC_IN1) U1.31(VDD_SOC_IN2) U1.39(VDD_SOC_IN3) U1.86(VDD_SOC_IN4) U1.102(VDD_SOC_IN5) U1.114(VDD_SOC_IN6) U1.134(VDD_SOC_IN7)
VDD_USB_3V: C79.1 C80.1 U1.61(VDD_USB_CAP)
VDDA_ADC_3P3_MCU: C6.1 C7.1 J3.2 R12.2 U1.73(VDDA_ADC_3P3)
VDDA_ADC_3V3: C47.1 J3.1 R12.1 R35.2
AUD_INT: U1.88(GPIO_AD_B1_04) ; also on sheet 8
CAN1_H: C88.2 D11.2(CATHODE2) FL1.1 J10.1 R76.2 R77.1
CAN1_L: C90.1 D11.1(CATHODE1) FL1.2 J10.3 R78.2 R79.2
CAN1_RX: U1.32(GPIO_SD_B1_01) U9.4(RXD)
CAN1_TX: U1.33(GPIO_SD_B1_00) U9.1(TXD)
CAN_STBY: R74.1 U1.76(GPIO_AD_B1_13) ; also on sheet 15
CAN_VIO_3V3: C87.1 R72.1 R73.1 U9.5(VIO)
DC_5V_IN: C4.1 J2.1 Q1.1(D1) Q1.2(D2) Q1.5(D5) Q1.6(D6) Q1.7(D7) R1.1 R2.1 R6.1 TP1.1(Pin1)
DCDC_3V3: C171.1 J8.1 R15.1 R19.1 R28.1 R35.1 R37.1 R45.1 R47.1 R56.1 R64.1 R66.1 R72.2 R424.1 U27.A1(VIN) ; also on sheet 8 9 10 11 13 14 15
DCDC_3V3_PG: C57.1 C58.1 TP9.1(TP) U4.1(PG) U6.3(~{SHDN})
DCDC_OUT: C38.1 C39.1 J4.2 L1.1 R13.2
ENET_CRS_DV: R425.2 U1.97(GPIO_AD_B0_11) ; also on sheet 9 15
ENET_INT: U1.84(GPIO_AD_B1_06) ; also on sheet 9 15
ENET_MDC: U1.115(GPIO_EMC_41) ; also on sheet 9
ENET_MDIO: U1.116(GPIO_EMC_40) ; also on sheet 9
ENET_RST: R425.1 U1.107(GPIO_AD_B0_04) ; also on sheet 9 11 15
ENET_RXD0: U1.98(GPIO_AD_B0_10) ; also on sheet 9 15
ENET_RXD1: U1.99(GPIO_AD_B0_09) ; also on sheet 9 15
ENET_RXER: U1.96(GPIO_AD_B0_12) ; also on sheet 9 15
ENET_TX_CLK: U1.100(GPIO_AD_B0_08) ; also on sheet 9
ENET_TXD0: U1.94(GPIO_AD_B0_14) ; also on sheet 9 15
ENET_TXD1: U1.93(GPIO_AD_B0_15) ; also on sheet 9 15
ENET_TXEN: U1.95(GPIO_AD_B0_13) ; also on sheet 9 15
FlexSPI_CLK: U1.24(GPIO_SD_B1_07) ; also on sheet 14
FlexSPI_D0_A: U1.23(GPIO_SD_B1_08) ; also on sheet 14
FlexSPI_D1_A: U1.21(GPIO_SD_B1_10) ; also on sheet 14
FlexSPI_D2_A: U1.22(GPIO_SD_B1_09) ; also on sheet 14
FlexSPI_D3_A: U1.25(GPIO_SD_B1_06) ; also on sheet 14
FlexSPI_SS0: U1.19(GPIO_SD_B1_11) ; also on sheet 14
GPIO_AD_B0_05: D5.C(CATHODE) U1.106(GPIO_AD_B0_05) ; also on sheet 15
GPIO_AD_B0_06: U1.105(GPIO_AD_B0_06) ; also on sheet 11 15
GPIO_AD_B0_07: U1.101(GPIO_AD_B0_07) ; also on sheet 11 15
GPIO_AD_B1_07: Q8.2(GATE) R55.1 U1.83(GPIO_AD_B1_07) ; also on sheet 15
GPIO_AD_B1_08: U1.82(GPIO_AD_B1_08) ; also on sheet 15
GPIO_AD_B1_09: U1.81(GPIO_AD_B1_09) ; also on sheet 15
GPIO_AD_B1_10: R69.1 U1.80(GPIO_AD_B1_10) ; also on sheet 15
GPIO_AD_B1_11: Q9.2(GATE) R68.2 R424.2 U1.79(GPIO_AD_B1_11) ; also on sheet 15
GPIO_AD_B1_12: R65.1 U1.78(GPIO_AD_B1_12) ; also on sheet 15
GPIO_AD_B1_14: U1.75(GPIO_AD_B1_14) ; also on sheet 8 15
GPIO_AD_B1_15: U1.74(GPIO_AD_B1_15) ; also on sheet 8 15
GPIO_SD_B1_02: TP11.1(TP) U1.30(GPIO_SD_B1_02) ; also on sheet 13 15
GPIO_SD_B1_03: TP12.1(TP) U1.28(GPIO_SD_B1_03) ; also on sheet 13 15
INT1_COMBO: R316.1 U1.27(GPIO_SD_B1_04) ; also on sheet 13
INT2_COMBO: U1.26(GPIO_SD_B1_05) ; also on sheet 13
JTAG_MOD: R57.1 U1.109(GPIO_AD_B0_02)
JTAG_TCK: U1.110(GPIO_AD_B0_01) ; also on sheet 11 15
JTAG_TDI: C61.1 U1.108(GPIO_AD_B0_03) ; also on sheet 11 15
JTAG_TMS: U1.111(GPIO_AD_B0_00) ; also on sheet 11 15
MCU_DCDC_IN: C31.1 C32.1 C33.1 C35.1 J37.1 R33.1 R357.1 U1.34(DCDC_IN) U1.38(DCDC_IN_Q)
MCU_DCDC_IN_3V3: C55.1 J37.2 R44.2 R47.2 R357.2
NVCC_GPIO_3V3: C66.1 C67.1 C68.1 C69.1 C70.1 C71.1 C72.1 C73.1 C74.1 C176.1 C177.1 C178.1 R56.2 U1.11(NVCC_GPIO1) U1.20(NVCC_GPIO2) U1.29(NVCC_GPIO3) U1.77(NVCC_GPIO4) U1.104(NVCC_GPIO5) U1.112(NVCC_GPIO6) U1.144(NVCC_GPIO7)
NVCC_SD: C64.1 C65.1 R51.1 R52.1 R58.1 R59.1 R60.1 TP10.1(TP) U6.5(OUT)
ONOFF: C172.1 SW2.3(B1) SW2.4(B2) U1.49(ONOFF)
OTG1_DN: L4.1 R61.2 U1.62(USB_OTG1_DN)
OTG1_DP: L4.4 R63.2 U1.63(USB_OTG1_DP)
PMIC_ON_REQ: R41.2 R43.2 U1.53(PMIC_ON_REQ)
POR_B: C28.1 D8.C R22.2 R26.2 U1.50(~{POR}) ; also on sheet 11 15
POR_BUTTON: C173.1 R43.1 R50.1 SW3.3(B1) SW3.4(B2)
SAI1_MCLK: U1.92(GPIO_AD_B1_00) ; also on sheet 8
SAI1_RXD: U1.87(GPIO_AD_B1_05) ; also on sheet 8
SAI1_TX_BCLK: U1.91(GPIO_AD_B1_01) ; also on sheet 8
SAI1_TX_SYNC: U1.90(GPIO_AD_B1_02) ; also on sheet 8
SAI1_TXD: U1.89(GPIO_AD_B1_03) ; also on sheet 8
SD1_CLK: U1.45(GPIO_SD_B0_03) ; also on sheet 14
SD1_CMD: R59.2 U1.46(GPIO_SD_B0_02) ; also on sheet 14
SD1_D0: R58.2 U1.43(GPIO_SD_B0_04) ; also on sheet 14
SD1_D1: U1.42(GPIO_SD_B0_05) ; also on sheet 14
SD1_D2: U1.48(GPIO_SD_B0_00) ; also on sheet 14
SD1_D3: U1.47(GPIO_SD_B0_01) ; also on sheet 14
SD_CD_SW: U1.41(GPIO_SD_B0_06) ; also on sheet 14
SD_PWREN: D7.C R316.2
SEMC_A0: U1.142(GPIO_EMC_16) ; also on sheet 10
SEMC_A1: U1.141(GPIO_EMC_17) ; also on sheet 10
SEMC_A2: U1.140(GPIO_EMC_18) ; also on sheet 10
SEMC_A3: U1.139(GPIO_EMC_19) ; also on sheet 10
SEMC_A4: U1.138(GPIO_EMC_20) ; also on sheet 10
SEMC_A5: U1.137(GPIO_EMC_21) ; also on sheet 10
SEMC_A6: U1.136(GPIO_EMC_22) ; also on sheet 10
SEMC_A7: U1.133(GPIO_EMC_23) ; also on sheet 10
SEMC_A8: U1.132(GPIO_EMC_24) ; also on sheet 10
SEMC_A9: U1.131(GPIO_EMC_25) ; also on sheet 10
SEMC_A10: U1.143(GPIO_EMC_15) ; also on sheet 10
SEMC_A11: U1.130(GPIO_EMC_26) ; also on sheet 10
SEMC_A12: U1.129(GPIO_EMC_27) ; also on sheet 10
SEMC_BA0: U1.2(GPIO_EMC_13) ; also on sheet 10
SEMC_BA1: U1.1(GPIO_EMC_14) ; also on sheet 10
SEMC_CAS: U1.7(GPIO_EMC_10) ; also on sheet 10
SEMC_CKE: U1.127(GPIO_EMC_29) ; also on sheet 10
SEMC_CLK: U1.126(GPIO_EMC_30) ; also on sheet 10
SEMC_CS0: U1.3(GPIO_EMC_12) ; also on sheet 10
SEMC_D0: U1.18(GPIO_EMC_00) ; also on sheet 10
SEMC_D1: U1.17(GPIO_EMC_01) ; also on sheet 10
SEMC_D2: U1.16(GPIO_EMC_02) ; also on sheet 10
SEMC_D3: U1.15(GPIO_EMC_03) ; also on sheet 10
SEMC_D4: U1.14(GPIO_EMC_04) ; also on sheet 10
SEMC_D5: U1.13(GPIO_EMC_05) ; also on sheet 10
SEMC_D6: U1.12(GPIO_EMC_06) ; also on sheet 10
SEMC_D7: U1.10(GPIO_EMC_07) ; also on sheet 10
SEMC_D8: U1.124(GPIO_EMC_32) ; also on sheet 10
SEMC_D9: U1.123(GPIO_EMC_33) ; also on sheet 10
SEMC_D10: U1.122(GPIO_EMC_34) ; also on sheet 10
SEMC_D11: U1.121(GPIO_EMC_35) ; also on sheet 10
SEMC_D12: U1.120(GPIO_EMC_36) ; also on sheet 10
SEMC_D13: U1.119(GPIO_EMC_37) ; also on sheet 10
SEMC_D14: U1.118(GPIO_EMC_38) ; also on sheet 10
SEMC_D15: U1.117(GPIO_EMC_39) ; also on sheet 10
SEMC_DM0: U1.9(GPIO_EMC_08) ; also on sheet 10
SEMC_DM1: U1.125(GPIO_EMC_31) ; also on sheet 10
SEMC_DQS: C75.1 U1.128(GPIO_EMC_28)
SEMC_RAS: U1.4(GPIO_EMC_11) ; also on sheet 10
SEMC_WE: U1.8(GPIO_EMC_09) ; also on sheet 10
USER_BUTTON: C174.1 SW4.3(B1) SW4.4(B2) TP6.1(TP) U1.52(WAKEUP)
VLDO_3V3: C42.1 C43.1 R32.1 R36.1 R44.1 R49.1 U3.5(OUT)
VSD_3V3: C30.1 U27.A2(VOUT) ; also on sheet 14
WALL_OV_BASE: Q3.1(B) R5.2
WALL_OV_CTL: D1.C(CATHODE) R3.2 R5.1
WALL_OVP_LED: D2.A Q3.3(C) R10.1
N99781517: D4.C D6.C J6.1 R16.1 R17.2
N99781633: C21.1 C22.1 U1.65(VDD_HIGH_CAP)
N99781636: C24.1 U1.56(VDD_SNVS_CAP)
N99781637: C25.1 C26.1 U1.72(NVCC_PLL)
N99781671: L1.2 U1.36(DCDC_LP)
N99781682: C44.1 U1.57(RTC_XTALI) Y2.1
N99781687: C45.1 U1.58(RTC_XTALO) Y2.2
N99781695: C37.1 R30.2 U1.68(XTALO) Y4.1
N99781702: C36.1 R30.1 R31.1 U1.67(XTALI) Y4.3
N99781716: C29.1 R20.2 R21.1 U2.3(VCC)
N99781728: R21.2 R22.1 U2.2(~{RESET})
N99781740: C61.2 D10.C R53.1
N99781746: D9.A D10.A R46.1 U5.3(~{MR})
N99781747: C52.1 C53.1 J8.2 L2.2 R40.1 TP8.1(TP) U4.5(OUT)
N99781749: C54.1 R39.2 R41.1 R46.2 U4.8(EN) U5.2(~{RESET})
N99781753: C59.1 D9.C R50.2
N99781762: C49.1 C50.1 C51.1 R38.2 R39.1 U4.2(VIN)
N99781782: R40.2 R42.1 U4.7(FB)
N99781791: L2.1 U4.3(SW)
N99808656: C76.1 C77.1 R60.2 U1.44(NVCC_SD0)
N99833003: J9.S1(SHLD1) J9.S2(SHLD2) J9.S3(SHLD3) J9.S4(SHLD4) L5.1
N99833017: J9.1(P1) L3.1 U8.6(VBUS)
N99833020: J9.4(P4) R68.1 U8.3(USB_ID)
N99833038: J9.2(P2) L4.2 R61.1 U8.1(DM)
N99833040: J9.3(P3) L4.3 R63.1 U8.2(DP)
N100002783: C46.1 R33.2 U1.37(DCDC_PSWITCH)
N100054133: Q4.1(GATE) R10.2 R11.1
N100054172: C1.1 C2.1 C3.1 J1.1(A1) JP1.2 Q2.1(D1) Q2.2(D2) Q2.5(D5) Q2.6(D6) Q2.7(D7) TVS1.2(A2)
N100054253: C5.2 D2.C Q2.3(G) R4.2 R8.1
N100054255: R8.2 R9.1
N100054257: R9.2 SW1.5(COMMON2)
N100054299: C5.1 JP1.1 Q1.4(S1) Q1.8(S2) Q2.4(S1) Q2.8(S2) Q3.2(E) R1.2 R2.2 R3.1 R4.1
N100054525: D3.3(ANODE2) R7.2
N100054552: D3.1(ANODE1) R6.2
N100054568: D3.2(CATHODE1) Q4.3(DRAIN)
N100054652: J1.2(B1) J1.4(B2) J1.6(B3) L20.1
N100756566: TP7.1(TP) U1.71(GPANAIO)
N100757315: TP13.1(TP) U1.66(~{USB_OTG1_CHD})
N100872888: R19.2 R20.1 R25.2
N100979684: R32.2 R34.1 U3.4(FB)
N101108824: D5.A(ANODE) R15.2
N101139052: C82.1 C83.1 R62.2 U7.B1(VINT1) U7.B2(VINT2) U7.C1(VINT3)
N101140611: Q9.3(DRAIN) R66.2 R69.2 R70.1 U7.A1(EN)
N101140956: R64.2 R65.2 U7.A2(~{FAULT})
N101141371: R67.1 U7.A3(ILIM)
N101253829: C85.1 C86.1 R71.2 U9.3(VCC)
N101254531: C89.1 R77.2 R78.1
N101254622: FL1.4 R76.1 U9.7(CANH)
N101254624: FL1.3 R79.1 U9.6(CANL)
N101255204: R73.2 R74.2 R75.1 U9.8(S)
N101312524: Q8.3(DRAIN) R52.2
N101312526: Q8.1(SOURCE) R51.2 R54.1 U6.4(FB)
N101449115: D7.A D8.A R28.2 R29.1
N101449483: R29.2 U27.B1(EN)
N101594808: TP25.1(TP) U1.54(PMIC_STBY_REQ)

Not connected (* = marked no-connect by the designer): SW1 1(NC1)* 2(COMMON1)* 4(NC2)*; U8 4(NC1)* 5(NC2)*

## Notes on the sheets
sheet 1
- MIMXRT1020-EVK
- Table of Content
- Revision History
- Page 1
- COVER
- Rev. Code
- Date
- By
- Description
- Page 2
- BLOCK DIAGRAM
- A1
- 2017-12-01
- Shawn Shi
- A1 Version for pilot board production
- Page 3
- MAIN POWER
- A2
- 2018-1-30
- Shawn Shi
- SD_PWEN change to GPIO_SD_B1_04 pin,DNP C141, add R314,R315 to support SPI NAND boot, Delete R48, add J37
- Page 4
- POWER DOMAIN
- 2018-4-24
- Shawn Shi
- A3
- Update BOM only,  Change R22 from 1K to 0 ohm, DNP C6, DNP U26
- Page 5
- MIMXRT1021DAG5A
- B1
- 2018-10-17
- Shawn Shi
- Change K20 based OPENSDA to LPC4322 based FREELINK, change load capacitor value of 32.768 KHz OSC,
  Route SWO trace signal to JTAG
- Page 6
- USB
- Page 7
- CAN
- Page 8
- AUDIO
- Page 9
- ETHERNET
- Page 10
- SD/FLASH
- Page 11
- ARDUINO/JTAG
- Page 12
- SDRAM
- FREELINK
- Page 13
- Page 14
- BOOT
- Page 15
- MISC
- Page 16
- Page 17
- Page 18
- Page 19
- Page 20
- Page 21
- Page 22
- Page 23
- Page 24
- Page 25
- Page 26
- Page 26
- Page 27
- Page 28
- 3. Device type number is for reference only. The number
  varies with the manufacturer.
- 1. Unless Otherwise Specified:
- All resistors are in ohms, 1/16 Watt,0402
- 4. Special signal usage:
- All capacitors are in uF,0402
- _B Denotes - Active-Low Signal
- All voltages are DC
- <> or [] Denotes - Vectored Signals
- All polarized capacitors are aluminum electrolytic
- 5. Interpret diagram in accordance with American
  National Standards Institute specifications, current
  revision, with the exception of logic block symbology.
- 2. Interrupted lines coded with the same letter or letter
      combinations are electrically connected.
sheet 2
- #####  Blcok Diagram Rev B1 #####
- # MIMXRT1020-EVK
- Ethernet x1 (RMII)
- CAN x1
- USB OTG
- TJA1057GT/3
- 100Base-TMicrel KSZ8081
- RMII
- USB OTG1
- CAN
- QSPI Flash
- FlexSPI
- USB/5V
- FlexSPI
- POWER
- POWER
- ISSI IS25LP064A-JBLE
- NXP
    IMXRT1020
- SDRAM
- x16 bits
- SDRAM
- SD0
- SD SLOT
- SDHC
- Micron256Mb:
  MT48LC16M16A2P
- T-Flash
- JTAG/OPENSDA
- I2C/INT
- I2S
- Arduino
- JTAG/OPENSDA
- Motion Sensors
- CODEC
- ARDUINO
- Wolfson WM8960
- PIN Header
- PIN Header
- Combo FXOS8700CQ
- HP
- MIC
sheet 3
- Main Power
- Barrel Connector
- Default: 1-2
- Board Mounting Holes
- Ground TPs
- Layout Note: Place Ground TPs
  to assist signal measurement.
sheet 4
- USER LED
- Up to 34.5mA
- Default: 1-2
- BUTTON
- Default: 1-2
- Up to 75mA
- # CPU ONOFF Button
- Default: 1-2
- VDDA_2P5_CAP
- VDDA_1P1_CAP
- # System Reset Button
- Up to 1mA
- Default: 1-2
- # System Reset Button
- BATTERY SUPPLY
- SD CARD POWER SWITCH
- # Open
  Drain
- 3V3 LDO for SNVS
- FOR OSC STARTUP
- Vfb=1V
- PSWITCH RC Delay
- ADC
- SNVS
- VDDHIGH / NVCC_xxx
- Current 2A
  I_Quiescent : 40μA
- 5V
- Vfb=0.6V
- DCDC_IN
- VDD_HIGH_IN
- # R26/R30 = 4.5
- # PG pin is pulled up to
  VIN by the internal
  resistor 500K OHM
- NVCC_SD <SD3.0>
- MAX 350 mA
- # GPIO/WDOG PWR OFF->ON
- Vfb=1V
- # 1.8V/3.3V
- # Default: 3.3V
- # R1/R2 = (Vo-Vfb)/Vfb
- # FB = 1.0V
- # 1.8V: R1/R2 = 0.8/ 1: 160K/200K
- # 3.3V: R1/R2 = 2.3/1 : 464K/200K
sheet 5
- MCU PINOUT
- VALUE TBD
- CLKO1
- CLKO2
- Up to 25 mA
sheet 6
- USB POWER
- USB OTG
- 0ohm and inductor share same package
- MAX 500 mA @5V
sheet 7
- CAN  BUS
- MAX 70 mA @5V
- Standby: 5 uA
